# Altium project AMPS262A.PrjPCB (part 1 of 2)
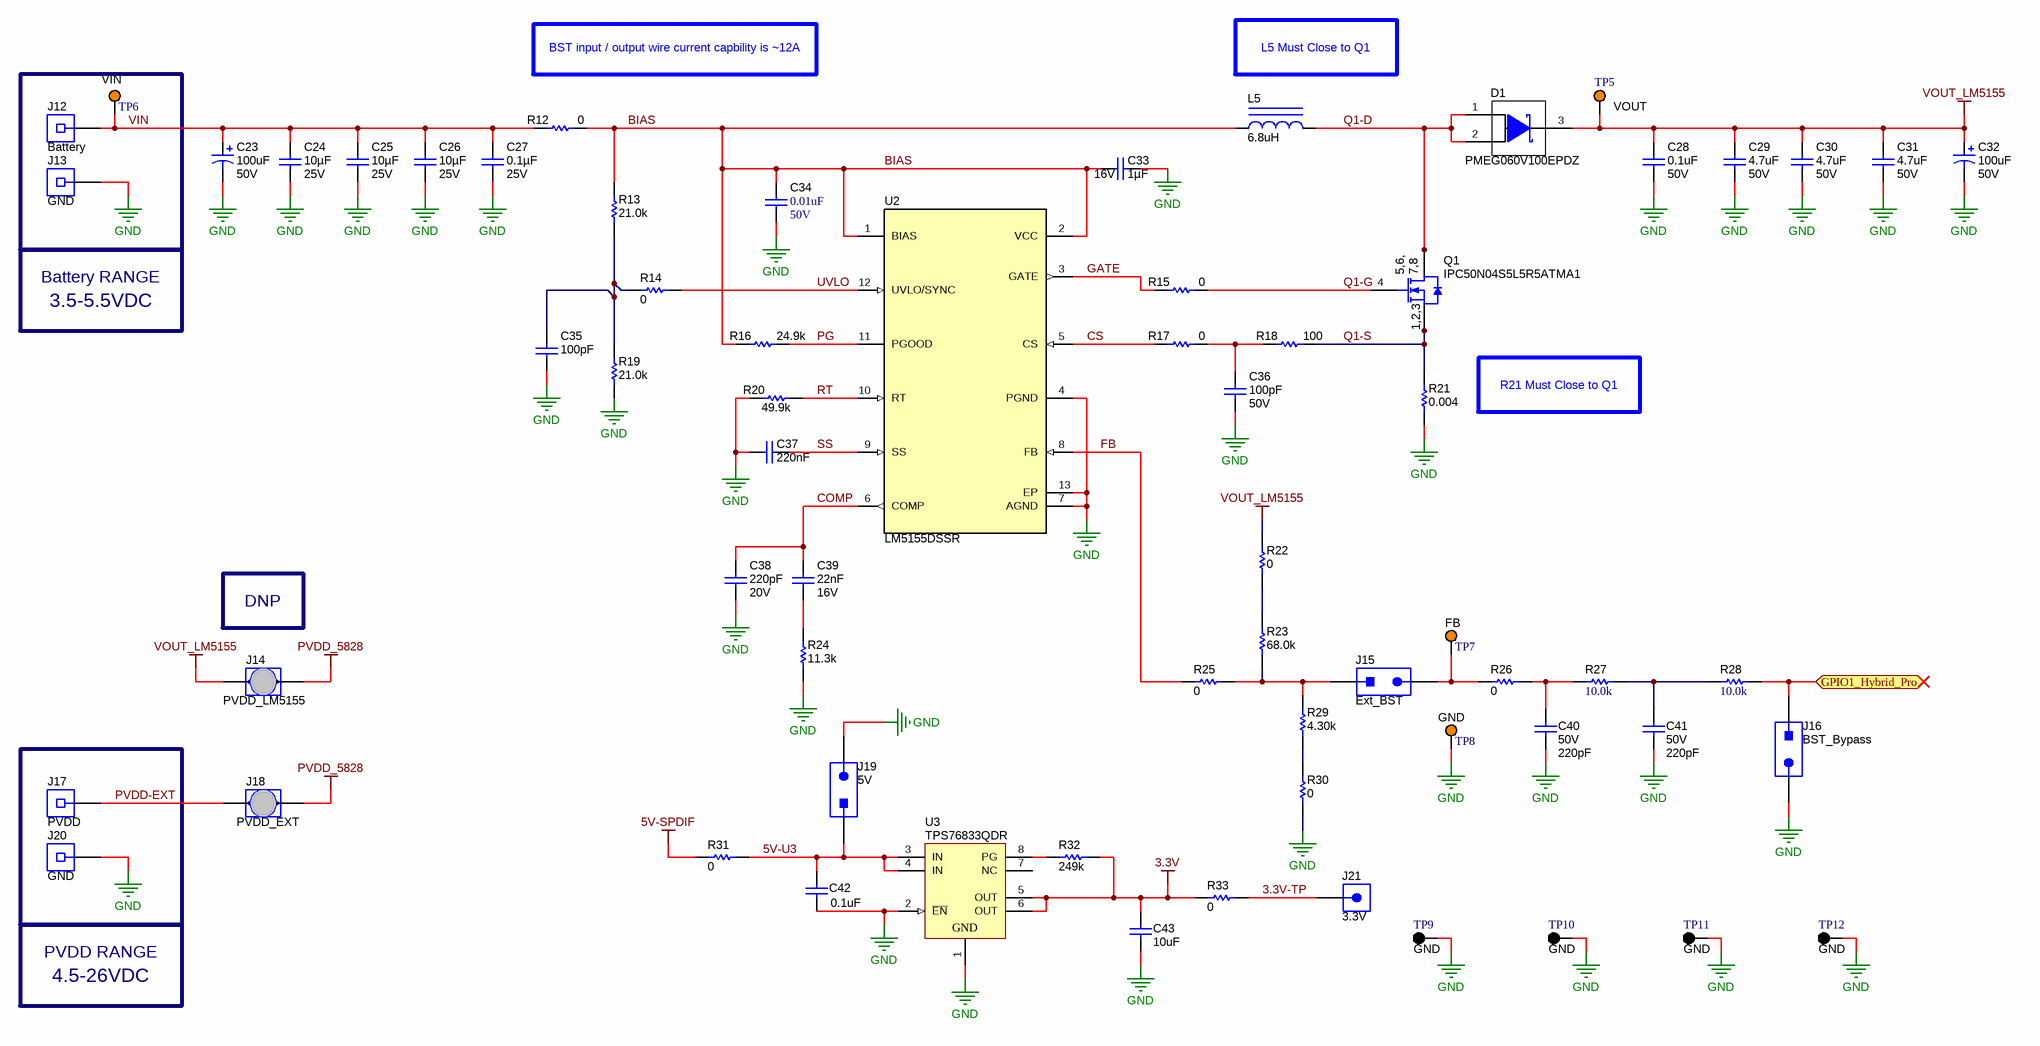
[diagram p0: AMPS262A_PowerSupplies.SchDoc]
CopyrightYear: 2021; PCB_Layout: Krypton Solutions; PCB_Rev: A; PRJ_Customer: Public Release; PRJ_Engineer: Ramsey Foote; PRJ_Number: AMPS262; PRJ_Title: TAS5830 Evaluation Module; SCH_Rev: A; TechSupport: http://www.ti.com/support; TID: N/A
5 sheets, 325 parts. Net scope: flat (ports and power ports of the same name join across sheets).
Board file: AMPS262A.PcbDoc
Sheets:
  AMPS262A_PowerSupplies.SchDoc
  AMPS262A_Hardware.SchDoc
  AMPS262A_USB.SchDoc
  AMPS262A_SPDIF_I2S_PSIA.SchDoc
  AMPS262A_TAS5830_IO.SchDoc

## Sheet AMPS262A_PowerSupplies.SchDoc
size A2; Date: Not shown in title block; ApprovedBy: Not shown in title block; CheckedBy: Not shown in title block; Author: Not shown in title block; CompanyName: Not shown in title block; Engineer: Not shown in title block; Organization: Not shown in title block; Address1: Not shown in title block; Address2: Not shown in title block; Address3: Not shown in title block; Address4: Not shown in title block; DocumentNumber: 2; Revision: Use project parameter SCH_Rev; SheetNumber: 1; SheetTotal: 5; PageSetup: Record=PageOptions¦CenterHorizontal=True¦CenterVertical=True¦PrintScale=1.00¦XCorrection=1.00¦YCorrection=1.00¦PrintKind=0¦BorderSize=5000000¦LeftOffset=0¦BottomOffset=0¦Orientation=2¦PaperLength=1000¦PaperWidth=1000¦Scale=100¦PaperSource=15¦PrintQuality=600¦MediaType=1¦DitherType=10¦PaperKind=Letter¦PrintScaleMode=1

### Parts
C23  VDC_V: 50V  ValueDisplayed: 100uF  [SM_RADIAL_10BMM]  (hidden comment: +)
C24  VDC_V: 25V  ValueDisplayed: 10µF  [0603L]  (hidden comment: GRM188R61E106KA73D)
C25  VDC_V: 25V  ValueDisplayed: 10µF  [0603L]  (hidden comment: GRM188R61E106KA73D)
C26  VDC_V: 25V  ValueDisplayed: 10µF  [0603L]  (hidden comment: GRM188R61E106KA73D)
C27  VDC_V: 25V  ValueDisplayed: 0.1µF  [0402L]  (hidden comment: CGA2B3X7R1E104K050BB)
C28  Cap_F: 0.1uF  VDC_V: 50V  [0603L]  (hidden comment: CGA3E2X7R1H104K080AA)
C29  VDC_V: 50V  ValueDisplayed: 4.7uF  [1210_280]  (hidden comment: CGA6P3X7R1H475K250AB)
C30  VDC_V: 50V  ValueDisplayed: 4.7uF  [1210_280]  (hidden comment: CGA6P3X7R1H475K250AB)
C31  VDC_V: 50V  ValueDisplayed: 4.7uF  [1210_280]  (hidden comment: CGA6P3X7R1H475K250AB)
C32  VDC_V: 50V  ValueDisplayed: 100uF  [HXB_JA0]  (hidden comment: +)
C33  Cap_F: 1µF  VDC_V: 16V  [0603L]  (hidden comment: GCM188R71C105MA64D)
C34  VDC_V: 50V  ValueDisplayed: 0.01uF  [0603L]  (hidden comment: GCM188R71H103KA37D)
C35  ValueDisplayed: 100pF  [0603L]  (hidden comment: DNP)
C36  VDC_V: 50V  ValueDisplayed: 100pF  [0603L]  (hidden comment: C0603C101F5GACTU)
C37  Cap_F: 220nF  [0603L]  (hidden comment: CGA3E3X7R1H224K080AB)
C38  VDC_V: 20V  ValueDisplayed: 220pF  [0603L]  (hidden comment: CGA3E2C0G1H221J080AA)
C39  Cap_F: 22nF  VDC_V: 16V  [0603L]  (hidden comment: C0603C223K4RACTU)
C40  VDC_V: 50V  ValueDisplayed: 220pF  [0402]  (hidden comment: CGA2B2C0G1H221J050BA)
C41  VDC_V: 50V  ValueDisplayed: 220pF  [0402]  (hidden comment: CGA2B2C0G1H221J050BA)
C42  ValueDisplayed: 0.1uF  [0402L]  (hidden comment: 885012205037)
C43  ValueDisplayed: 10uF  [0603L]  (hidden comment: Capacitor)
D1  PMEG060V100EPDZ  [SOT1289]
J12  Battery  [Keystone_7006]
J13  GND  [Keystone_7007]
J14  Note: PVDD_LM5155  [HARWIN_S1911-46R]  (hidden comment: DNP)
J15  Ext_BST  [Sullins_PBC02SAAN]
J16  BST_Bypass  [Sullins_PBC02SAAN]
J17  PVDD  [Keystone_7006]
J18  PVDD_EXT  [HARWIN_S1911-46R]
J19  5V  [Sullins_PBC02SAAN]
J20  GND  [Keystone_7007]
J21  3.3V  [CONN_1040]
L5  ValueDisplayed: 6.8uH  [XAL1010]  (hidden comment: XAL1010-682MEB)
Q1  IPC50N04S5L5R5ATMA1  [PG-TDSON-8-33]
R12  ValueDisplayed: 0  [2512_WIDE_VISHAY]  (hidden comment: RCL12250000Z0EG)
R13  ValueDisplayed: 21.0k  [0603]  (hidden comment: RC0603FR-0721KL)
R14  ValueDisplayed: 0  [0603L]  (hidden comment: RMCF0603ZT0R00)
R15  ValueDisplayed: 0  [0603L]  (hidden comment: RC0603JR-070RL)
R16  ValueDisplayed: 24.9k  [0603L]  (hidden comment: RC0603FR-0724K9L)
R17  ValueDisplayed: 0  [0603L]  (hidden comment: RC0603JR-070RL)
R18  ValueDisplayed: 100  [0603L]  (hidden comment: RC0603FR-07100RL)
R19  ValueDisplayed: 21.0k  [0603]  (hidden comment: RC0603FR-0721KL)
R20  ValueDisplayed: 49.9k  [0603L]  (hidden comment: CRCW060349K9FKEA)
R21  ValueDisplayed: 0.004  [ERJMS4S]  (hidden comment: ERJ-MS4SF4M0U)
R22  ValueDisplayed: 0  [0603L]  (hidden comment: RC0603JR-070RL)
R23  ValueDisplayed: 68.0k  [0603]  (hidden comment: RC0603FR-0768KL)
R24  ValueDisplayed: 11.3k  [0603L]  (hidden comment: CRCW060311K3FKEA)
R25  ValueDisplayed: 0  [0603L]  (hidden comment: RC0603JR-070RL)
R26  ValueDisplayed: 0  [0603L]  (hidden comment: RC0603JR-070RL)
R27  ValueDisplayed: 10.0k  [0603]  (hidden comment: ERJ-3EKF1002V)
R28  ValueDisplayed: 10.0k  [0603]  (hidden comment: ERJ-3EKF1002V)
R29  ValueDisplayed: 4.30k  [0603]  (hidden comment: RC0603FR-074K3L)
R30  ValueDisplayed: 0  [0603L]  (hidden comment: RC0603JR-070RL)
R31  ValueDisplayed: 0  [0805L]  (hidden comment: RC0805JR-070RL)
R32  ValueDisplayed: 249k  [0603L]  (hidden comment: RC0603FR-07249KL)
R33  ValueDisplayed: 0  [0805L]  (hidden comment: RC0805JR-070RL)
TP5  VOUT  [Keystone5003]
TP6  VIN  [Keystone5003]
TP7  FB  [Keystone5003]
TP8  GND  [Keystone5003]
TP9  GND  [Keystone5006]
TP10  GND  [Keystone5006]
TP11  GND  [Keystone5006]
TP12  GND  [Keystone5006]
U2  LM5155DSSR  [DSS0012B]
U3  PartNumber: TPS76833QDR  [D0008A_M]  (hidden comment: TI-TPS7XXXXD8_A)

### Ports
GPIO1_Hybrid_Pro (bidir)

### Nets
3.3V: C43.1 R32.2 R33.1 U3.5(OUT) U3.6(OUT)
5V-SPDIF: R31.1
GND: C23.2(-) C24.2 C25.2 C26.2 C27.2 C28.2 C29.2 C30.2 C31.2 C32.2(-) C33.1 C34.2 C35.2 C36.2 C37.1 C38.2 C40.2 C41.2 C42.1 C43.2 J13.1 J16.2 J19.2 J20.1 R19.1 R20.2 R21.1 R24.1 R30.1 TP8.1 TP9.1 TP10.1 TP11.1 TP12.1 U2.4(PGND) U2.7(AGND) U2.13(EP) U3.1(GND) U3.2(~{EN})
PVDD_5828: J14.2 J18.2
VOUT_LM5155: C28.1 C29.1 C30.1 C31.1 C32.1(+) D1.3(K) J14.1 R22.2 TP5.1
3.3V-TP: J21.1 R33.2
5V-U3: C42.2 J19.1 R31.2 U3.3(IN) U3.4(IN)
BIAS: C33.2 C34.1 L5.1 R12.2 R13.2 R16.1 U2.1(BIAS) U2.2(VCC)
COMP: C38.1 C39.1 U2.6(COMP)
CS: R17.1 U2.5(CS)
FB: R25.1 U2.8(FB)
GATE: R15.1 U2.3(GATE)
GPIO1_Hybrid_Pro: J16.1 R28.2 ; port GPIO1_Hybrid_Pro
PG: R16.2 U2.11(PGOOD)
PVDD-EXT: J17.1 J18.1
Q1-D: D1.1(A) D1.2(A) L5.2 Q1.5(D) Q1.6(D) Q1.7(D) Q1.8(D)
Q1-G: Q1.4(G) R15.2
Q1-S: Q1.1(S) Q1.2(S) Q1.3(S) R18.2 R21.2
RT: R20.1 U2.10(RT)
SS: C37.2 U2.9(SS)
UVLO: R14.2 U2.12(UVLO/SYNC)
VIN: C23.1(+) C24.1 C25.1 C26.1 C27.1 J12.1 R12.1 TP6.1
NetC35_1: C35.1 R13.1 R14.1 R19.2
NetC36_1: C36.1 R17.2 R18.1
NetC39_2: C39.2 R24.2
NetC40_1: C40.1 R26.2 R27.1
NetC41_1: C41.1 R27.2 R28.1
NetJ15_1: J15.1 R23.1 R25.2 R29.2
NetJ15_2: J15.2 R26.1 TP7.1
NetR22_1: R22.1 R23.2
NetR29_1: R29.1 R30.2
NetR32_1: R32.1 U3.8(PG)

Not connected (* = marked no-connect by the designer): U3 7(NC)

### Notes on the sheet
- BST input / output wire current capbility is
  2A
- L5 Must Close to Q1
- Battery RANGE
- 3.5-5.5VDC
- R21 Must Close to Q1
- DNP
- PVDD RANGE
- 4.5-26VDC

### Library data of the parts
C23 = CMP-0012596-3: CAP, Polymer Hybrid, 100 uF, 50 V, +/- 20%, 28 ohm, 10x10 SMD; Manufacturer: Panasonic; PartNumber: EEHZC1H101P; Alternate Manufacturer: Cornell Dubilier Electronics (CDE); Alternate PartNumber: HZA107M050G24VT-F; TaMin_C: -55°C; ESR_ohm: 28; Polarized: Y; SizeAreaWB_mm2: 159.9; Value1: 28 ohm; Value: 100uF; TaMax_C: 125°C; SizeZ_mm: 10.2; SizeX_mm: 11; SizeY_mm: 10.3; SizeArea_mm2: 113.3; CompType: Capacitor; Cap_F: 100µF; IRMS_A: 1.6A; AEC Category: Q200
C24-C26 = CMP-0860569-1: CAP, CERM, 10 µF, 25 V,+/- 10%, X5R, 0603; Alternate Manufacturer: CAL-CHIP ELECTRONICS, INC.; Manufacturer: MuRata; Alternate PartNumber: GMC10X5R106K25NT; SizeZ_mm: 1; AEC Category: Q200; AEC Qualified: N; TaMin_C: -55°C; Cap_Case: 0603; SizeY_mm: 0.8; SizeAreaWB_mm2: 4.68; SizeArea_mm2: 1.28; TaMax_C: 85°C; SizeX_mm: 1.6; Value: 10uF; U/M: EA
C27 = CMP-0080610-1: CAP, CERM, 0.1 µF, 25 V,+/- 10%, X7R, AEC-Q200 Grade 1, 0402; Manufacturer: TDK; TaMin_C: -55°C; Polarized: N; SizeAreaWB_mm2: 3; U/M: EA; Value: 0.1uF; TaMax_C: 125°C; SizeZ_mm: 0.6; SizeX_mm: 1; SizeY_mm: 0.5; Cap_Case: 0402; AEC Qualified: Y; Cap_F: 100nF; AEC Category: Q200
C28 = CMP-0007078-4: CAP, CERM, 0.1 uF, 50 V, +/- 10%, X7R, AEC-Q200 Grade 1, 0603; Manufacturer: TDK; TaMin_C: -55°C; ESR_ohm: 0.0296; Polarized: N; SizeAreaWB_mm2: 4.68; Value1: 0.0296 ohm; U/M: EA; Value: 0.1uF; TaMax_C: 125°C; SizeZ_mm: 1; SizeX_mm: 1.6; SizeY_mm: 0.8; Cap_Case: 0603; SizeArea_mm2: 1.28; AEC Qualified: Y; IRMS_A: 971.99mA; AEC Category: Q200
C29-C31 = CMP-0009162-2: CAP, CERM, 4.7 uF, 50 V, +/- 10%, X7R, AEC-Q200 Grade 1, 1210; Manufacturer: TDK; TaMin_C: -55°C; ESR_ohm: 3.166m; Polarized: N; SizeAreaWB_mm2: 14.7; Value1: 0.003166 ohm; U/M: EA; Value: 4.7uF; TaMax_C: 125°C; SizeZ_mm: 2.8; SizeX_mm: 3.2; SizeY_mm: 2.5; SizeArea_mm2: 8; AEC Qualified: Y; Cap_F: 4.7µF; IRMS_A: 4.13311A; AEC Grade: 1; AEC Category: Q200
C32 = CMP-0012269-3: CAP, Aluminum Polymer, 100 uF, 50 V, +/- 20%, 0.025 ohm, AEC-Q200 Grade 2, D10xL10mm SMD; Manufacturer: Chemi-Con; PartNumber: HHXB500ARA101MJA0G; Alternate Manufacturer: Cornell Dubilier Electronics (CDE); Alternate PartNumber: HZA107M050G24VT-F; TaMin_C: -55°C; ESR_ohm: 0.025; Polarized: Y; Value: 100uF; TaMax_C: 105°C; Cap_Case: 10x10mm; CompType: Capacitor; Cap_F: 100µF; IRMS_A: 2A; AEC Grade: 2; AEC Category: Q200
C33 = CMP-0007137-5: CAP, CERM, 1 uF, 16 V, +/- 20%, X7R, AEC-Q200 Grade 1, 0603; Manufacturer: MuRata; TaMin_C: -55°C; Polarized: N; SizeAreaWB_mm2: 4.68; Value1: Unknown; U/M: EA; Value: 1uF; TaMax_C: 125°C; SizeZ_mm: 1; SizeX_mm: 1.6; SizeY_mm: 0.8; Cap_Case: 0603; SizeArea_mm2: 1.28; AEC Qualified: Y; AEC Category: Q200
C34 = CMP-0007143-4: CAP, CERM, 0.01 uF, 50 V, +/- 10%, X7R, AEC-Q200 Grade 1, 0603; Manufacturer: MuRata; TaMin_C: -55°C; Polarized: N; SizeAreaWB_mm2: 4.68; Value1: Unknown; U/M: EA; Value: 0.01uF; TaMax_C: 125°C; SizeZ_mm: 1; SizeX_mm: 1.6; SizeY_mm: 0.8; Cap_Case: 0603; SizeArea_mm2: 1.28; AEC Qualified: Y; Cap_F: 10nF; AEC Category: Q200
C35 = CMP-0080091-1: CAP, CERM, 100 pF, 50 V,+/- 1%, C0G/NP0, 0603; PartNumber: C0603C101F5GACTU; Manufacturer: Kemet; SizeAreaWB_mm2: 4.68; SizeArea_mm2: 1.28; AEC Qualified: N; AEC Category: Q200; Value: 100pF; TaMax_C: 125°C; SizeZ_mm: 1; Green_REACh: Passed; TaMin_C: -55°C; VDC_V: 50V; SizeY_mm: 0.8; Green_Lifecycle: Active; U/M: EA; SizeX_mm: 1.6; Cap_Case: 0603
C36 = CMP-0080091-1: CAP, CERM, 100 pF, 50 V,+/- 1%, C0G/NP0, 0603; Manufacturer: Kemet; SizeAreaWB_mm2: 4.68; SizeArea_mm2: 1.28; AEC Qualified: N; AEC Category: Q200; Value: 100pF; TaMax_C: 125°C; SizeZ_mm: 1; Green_REACh: Passed; TaMin_C: -55°C; SizeY_mm: 0.8; Green_Lifecycle: Active; U/M: EA; SizeX_mm: 1.6; Cap_Case: 0603
C37 = CMP-0007094-5: CAP, CERM, 0.22 uF, 50 V, +/- 10%, X7R, AEC-Q200 Grade 1, 0603; Manufacturer: TDK; TaMin_C: -55°C; ESR_ohm: 0.021699; Polarized: N; SizeAreaWB_mm2: 4.68; Value1: 0.021699 ohm; U/M: EA; Value: 0.22uF; TaMax_C: 125°C; SizeZ_mm: 1; SizeX_mm: 1.6; SizeY_mm: 0.8; Cap_Case: 0603; Value2: 50V; SizeArea_mm2: 1.28; AEC Qualified: Y; IRMS_A: 1.12496A; AEC Category: Q200
C38 = CMP-0007072-4: CAP, CERM, 220 pF, 20 V, +/- 5%, C0G/NP0, AEC-Q200 Grade 1, 0603; Manufacturer: TDK; TaMin_C: -55°C; Polarized: N; SizeAreaWB_mm2: 4.68; Value1: Unknown; U/M: EA; Value: 220pF; TaMax_C: 125°C; SizeZ_mm: 1; SizeX_mm: 1.6; SizeY_mm: 0.8; Cap_Case: 0603; SizeArea_mm2: 1.28; AEC Qualified: Y; AEC Category: Q200
C39 = CMP-0006900-4: CAP, CERM, 0.022 uF, 16 V, +/- 10%, X7R, 0603; Manufacturer: Kemet; TaMin_C: -55°C; Polarized: N; SizeAreaWB_mm2: 4.68; Value1: Unknown; U/M: EA; TaMax_C: 125°C; SizeZ_mm: 1; SizeX_mm: 1.6; SizeY_mm: 0.8; Cap_Case: 0603; SizeArea_mm2: 1.28; AEC Category: Q200
C40 C41 = CMP-0079606-1: CAP, CERM, 220 pF, 50 V,+/- 5%, C0G/NP0, AEC-Q200 Grade 1, 0402; Manufacturer: TDK; TaMin_C: -55°C; Polarized: N; SizeAreaWB_mm2: 3; U/M: EA; Value: 220pF; TaMax_C: 125°C; SizeZ_mm: 0.6; SizeX_mm: 1; SizeY_mm: 0.5; AEC Qualified: Y; AEC Category: Q200
C42 = CMP-0006228-2: CAP, CERM, 0.1 uF, 16 V, +/- 10%, X7R, 0402; Manufacturer: Wurth Elektronik; TaMin_C: -55°C; Polarized: N; SizeAreaWB_mm2: 3; Value1: Unknown; U/M: EA; Value: 0.1uF; TaMax_C: 125°C; SizeZ_mm: 0.6; SizeX_mm: 1; SizeY_mm: 0.5; Cap_Case: 0402; Value2: 16V; Cap_F: 100nF; AEC Category: Q200
C43 = CMP-0007003-5: CAP, CERM, 10 uF, 10 V, +/- 20%, X5R, 0603; PartNumber: C1608X5R1A106M080AC; Manufacturer: TDK; Polarized: N; Value: 10uF; U/M: EA; Cap_F: 10µF; ESR_ohm: 7.8m; Value1: 0.0078 ohm; VDC_V: 10V; IRMS_A: 1.85A; TaMin_C: -55°C; TaMax_C: 85°C; Cap_Case: 0603; SizeArea_mm2: 1.28; SizeAreaWB_mm2: 4.68; SizeX_mm: 1.6; SizeY_mm: 0.8; SizeZ_mm: 1; AEC Category: Q200
D1 = CMP-0028984-3: Diode, Schottky, 60 V, 10 A, AEC-Q101, CFP15; Manufacturer: Nexperia; Alternate Manufacturer: Vishay General Semiconductor - Diodes Division; Alternate PartNumber: V10PM6-M3/H; SizeArea_mm2: 27.95; SizeY_mm: 4.3; Vr_V: 60V; Value2: 0.56V; SizeX_mm: 6.5; SizeZ_mm: 0.82; AEC Category: Q101; Value1: 10A; Vf_V: 560mV; AEC Qualified: Y; SizeAreaWB_mm2: 53.55; TJmax_C: 175°C; Value: 60V
J12 J17 = CMP-0055127-1: Binding Post, RED, TH; PartNumber: 7006; Manufacturer: Keystone; CompType: Connector; Green_Lifecycle: Active; Green_REACh: Passed; CNHeader: FALSE
J13 J20 = CMP-0055128-1: Binding Post, BLACK, TH; PartNumber: 7007; Manufacturer: Keystone; CompType: Connector; Green_Lifecycle: Active; Green_REACh: Passed; CNHeader: FALSE
J14 J18 = CMP-0075020-1: JUMPER TIN SMD; Manufacturer: Harwin; PartNumber: S1911-46R; CNHeader: False; Green_Lifecycle: Active; Green_REACh: Passed; CompType: Jumper SMT
J15 J16 J19 = CMP-0054566-1: Header, 100mil, 2x1, Gold, TH; PartNumber: PBC02SAAN; Manufacturer: Sullins Connector Solutions; Pitch_mm: 2.54; Gender: Male; Shrouded: N; Row_Count: 1; Current_A: 3A; Voltage_V: 1.8kV; Cert_UL: Y; CNHeader: TRUE; CT: FALSE; Green_Lifecycle: Active; Green_REACh: Passed
J21 = CMP-0055161-1: Manufacturer: Keystone; PartNumber: 1040; CNHeader: FALSE; Green_Lifecycle: Active; Green_REACh: Passed; CompType: Test Point; CT: TRUE
L5 = CMP-0060953-1: Inductor, Shielded, Composite, 6.8 uH, 18.5 A, 0.01 ohm, SMD; Manufacturer: Coilcraft; Isat: 21.8A @ 30% inductance drop; Irms: 18.5A @ 40C rise; Green_Lifecycle: Not Set; SizeAreaWB_mm2: 159.6; DCR_ohm: 0.01; Green_REACh: Incomplete; Value: 6.8uH; Imax_A: 18.5A; SizeZ_mm: 10; SizeX_mm: 11.3; SizeArea_mm2: 113; Ind_H: 6.8µH; AEC Category: Q200
Q1 = CMP-0080659-3: MOSFET, N-CH, 40 V, 50 A, AEC-Q101, SON-8; Alternate PartNumber: CSD18510Q5B; Manufacturer: Infineon Technologies; Alternate Manufacturer: Texas Instruments; Value1: 0.0079 ohm; IdsMax_A: 50A; SizeZ_mm: 1.1; QgTyp_nC: 17; SizeX_mm: 6.44; AEC Category: Q101; Rdson45_ohm: 7.9m; VdsMax_V: 40V; Value: 40V; Value2: 17 nC; SizeAreaWB_mm2: 60.35; ChMode: Enhancement; SizeArea_mm2: 33.17; SizeY_mm: 5.15; Vgs_V: 16V; ChType: N; AEC Qualified: Y
R12 = CMP-0015368-2: RES, 0, 5%, 2 W, 2512 WIDE; Manufacturer: Vishay Draloric; Power_W: 2W; TempCo: ppm/C; Value_Code: 0000; U/M: EA; Value: 0; EIA_Code: E24; AEC Category: Q200
R13 R19 = CMP-0022914-5: RES, 21.0 k, 1%, 0.1 W, 0603; Manufacturer: Yageo; Power_W: 100mW; TempCo: 100 ppm/C; Value_Code: 21k0; Value: 21.0k; EIA_Code: E96; Res_ohm: 21k; SizeX_mm: 1.6; SizeY_mm: 0.8; SizeZ_mm: 1; Value2: 0.1W; SizeArea_mm2: 1.28; AEC Qualified: N; VDC_V: 75V; AEC Category: Q200; SizeAreaWB_mm2: 4.68
R14 = CMP-0023343-3: RES, 0, 1%, 0.1 W, AEC-Q200 Grade 0, 0603; Manufacturer: Stackpole Electronics Inc; Power_W: 100mW; TempCo: ppm/C; U/M: EA; Value: 0; SizeX_mm: 1.6; SizeY_mm: 0.8; SizeZ_mm: 1; Value2: 0.1W; SizeArea_mm2: 1.28; AEC Qualified: Y; AEC Category: Q200
R15 R17 R22 R25 R26 R30 = CMP-0025885-5: RES, 0, 5%, 0.1 W, 0603; Manufacturer: Yageo; Power_W: 100mW; TempCo: 200 ppm/C; Value_Code: 0000; Value: 0; EIA_Code: E24; SizeX_mm: 1.6; SizeZ_mm: 1; Value2: 0.1W; SizeArea_mm2: 1.28; AEC Qualified: N; VDC_V: 75V; AEC Category: Q200; SizeY_mm: 0.8; SizeAreaWB_mm2: 4.68
R16 = CMP-0022944-5: RES, 24.9 k, 1%, 0.1 W, 0603; Manufacturer: Yageo; Power_W: 100mW; TempCo: 100 ppm/C; Value_Code: 24k9; Value: 24.9k; EIA_Code: E96; SizeX_mm: 1.6; SizeY_mm: 0.8; SizeZ_mm: 1; Value2: 0.1W; SizeArea_mm2: 1.28; AEC Qualified: N; VDC_V: 75V; AEC Category: Q200; SizeAreaWB_mm2: 4.68
R18 = CMP-0022736-4: RES, 100, 1%, 0.1 W, 0603; Manufacturer: Yageo; Power_W: 100mW; TempCo: 100 ppm/C; Value_Code: 100R; Value: 100; EIA_Code: E96; SizeX_mm: 1.6; SizeY_mm: 0.8; SizeZ_mm: 1; Value2: 0.1W; SizeArea_mm2: 1.28; AEC Qualified: N; VDC_V: 75V; AEC Category: Q200; SizeAreaWB_mm2: 4.68
R20 = CMP-0022447-4: RES, 49.9 k, 1%, 0.1 W, AEC-Q200 Grade 0, 0603; Manufacturer: Vishay-Dale; Power_W: 100mW; TempCo: 100 ppm/C; Value_Code: 49k9; Value: 49.9k; EIA_Code: E96; SizeX_mm: 1.6; SizeY_mm: 0.8; SizeZ_mm: 1; Value2: 0.1W; SizeArea_mm2: 1.28; AEC Qualified: Y; VDC_V: 75V; AEC Category: Q200; AEC Grade: 0
R21 = CMP-0015077-2: RES, 0.004, 1%, 3 W, AEC-Q200 Grade 0, 6.4x3.2mm; Manufacturer: Panasonic; Alternate Manufacturer: TE Connectivity Passive Product; Alternate PartNumber: TLRP3A30WR004FTE; Power_W: 3W; TempCo: 75 ppm/C; SizeAreaWB_mm2: 43.68; Value_Code: 4L000; U/M: EA; Value: 0.004; Res_ohm: 4m; SizeX_mm: 6.4; SizeY_mm: 3.2; SizeZ_mm: 1.35; SizeArea_mm2: 20.48; AEC Qualified: Y; AEC Grade: 0; AEC Category: Q200
R23 = CMP-0023239-5: RES, 68.0 k, 1%, 0.1 W, 0603; Manufacturer: Yageo; Power_W: 100mW; TempCo: 100 ppm/C; Value_Code: 68k0; Value: 68.0k; Res_ohm: 68k; SizeX_mm: 1.6; SizeY_mm: 0.8; SizeZ_mm: 1; Value2: 0.1W; SizeArea_mm2: 1.28; AEC Qualified: N; VDC_V: 75V; AEC Category: Q200; SizeAreaWB_mm2: 4.68
R24 = CMP-0022017-4: RES, 11.3 k, 1%, 0.1 W, AEC-Q200 Grade 0, 0603; Manufacturer: Vishay-Dale; Power_W: 100mW; TempCo: 100 ppm/C; Value_Code: 11k3; Value: 11.3k; EIA_Code: E96; SizeX_mm: 1.6; SizeY_mm: 0.8; SizeZ_mm: 1; Value2: 0.1W; SizeArea_mm2: 1.28; AEC Qualified: Y; VDC_V: 75V; AEC Category: Q200; AEC Grade: 0
R27 R28 = CMP-0022684-3: RES, 10.0 k, 1%, 0.1 W, 0603; Manufacturer: Panasonic; Power_W: 100mW; TempCo: 100 ppm/C; Value_Code: 10k0; Value: 10.0k; EIA_Code: E96; Res_ohm: 10k; SizeX_mm: 1.6; SizeY_mm: 0.8; SizeZ_mm: 1; Value2: 0.1W; SizeArea_mm2: 1.28; AEC Category: Q200; VDC_V: 75V; U/M: EA
R29 = CMP-0023148-5: RES, 4.30 k, 1%, 0.1 W, 0603; Manufacturer: Yageo; Power_W: 100mW; TempCo: 100 ppm/C; Value_Code: 4k30; Value: 4.30k; Res_ohm: 4.3k; SizeX_mm: 1.6; SizeY_mm: 0.8; SizeZ_mm: 1; Value2: 0.1W; SizeArea_mm2: 1.28; AEC Qualified: N; VDC_V: 75V; AEC Category: Q200; SizeAreaWB_mm2: 4.68
R31 R33 = CMP-0020803-2: RES, 0, 5%, 0.125 W, 0805; Manufacturer: Yageo America; Power_W: 125mW; TempCo: 200 ppm/C; Value_Code: 0000; U/M: EA; Value: 0; EIA_Code: E24; SizeX_mm: 2; SizeY_mm: 1.25; SizeZ_mm: 1.45; Value2: 0.125W; SizeArea_mm2: 2.5; VDC_V: 150V; AEC Category: Q200
R32 = CMP-0022941-4: RES, 249 k, 1%, 0.1 W, 0603; Manufacturer: Yageo; Power_W: 100mW; TempCo: 100 ppm/C; Value: 249k; EIA_Code: E96; SizeX_mm: 1.6; SizeY_mm: 0.8; SizeZ_mm: 1; Value2: 0.1W; SizeArea_mm2: 1.28; AEC Qualified: N; VDC_V: 75V; AEC Category: Q200; SizeAreaWB_mm2: 4.68
TP5-TP8 = CMP-0055140-2: Test Point, Miniature, Orange, TH; Manufacturer: Keystone Electronics; ContactFinish: Silver; CNHeader: FALSE; CT: TRUE; Green_Lifecycle: Active; Green_REACh: Passed
TP9-TP12 = CMP-0055143-2: Test Point, Compact, Black, TH; Manufacturer: Keystone Electronics; CNHeader: FALSE; ContactFinish: Silver; CT: TRUE; Green_Lifecycle: Active; Green_REACh: Passed
U2 = CMP-0085413-1: 2.2-MHz Wide Input Nonsynchronous Boost, Sepic, Flyback Controller, DSS0012B (WSON-12); Alternate Manufacturer: Texas Instruments; Alternate PartNumber: LM5155DSST; SizeAreaWB_mm2: 12; SizeX_mm: 2; SizeZ_mm: 0.8; CompType: IC; SizeArea_mm2: 6; AEC Category: Q200; AEC Qualified: N; SizeY_mm: 3
U3 = CMP-0036485-1: Single Output Fast Transient Response LDO, 1 A, Fixed 3.3 V Output, 2.7 to 10 V Input, with Low IQ, 8-pin SOIC (D), -40 to 125 degC, Green (RoHS & no Sb/Br); Manufacturer: Texas Instruments; Accuracy(%): 2; Fixed Output Options(V): 3.3; Iout(Max)(A): 1; Iq(Typ)(mA): 0.08; Power Good: TRUE; SubFamily: Single Channel LDO; Vdo(Typ)(mV): 350; Vin(Max)(V): 10; Vin(Min)(V): 2.7

## Sheet AMPS262A_Hardware.SchDoc
size A4; Date: Not shown in title block; ApprovedBy: Not shown in title block; CheckedBy: Not shown in title block; Author: Not shown in title block; CompanyName: Not shown in title block; Engineer: Not shown in title block; Organization: Not shown in title block; Address1: Not shown in title block; Address2: Not shown in title block; Address3: Not shown in title block; Address4: Not shown in title block; DocumentNumber: 2; Revision: Use project parameter SCH_Rev; SheetNumber: 2; SheetTotal: 5; PageSetup: Record=PageOptions¦CenterHorizontal=True¦CenterVertical=True¦PrintScale=1.00¦XCorrection=1.00¦YCorrection=1.00¦PrintKind=0¦BorderSize=5000000¦LeftOffset=0¦BottomOffset=0¦Orientation=2¦PaperLength=1000¦PaperWidth=1000¦Scale=100¦PaperSource=15¦PrintQuality=600¦MediaType=1¦DitherType=10¦PaperKind=Letter¦PrintScaleMode=1
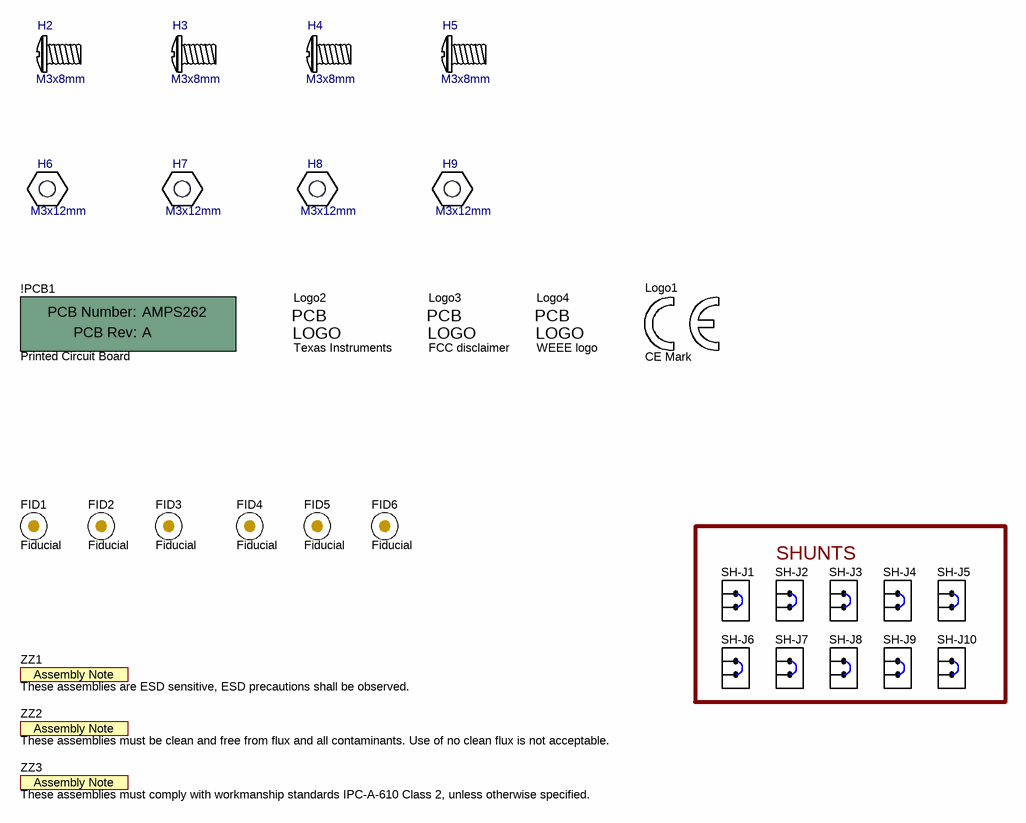
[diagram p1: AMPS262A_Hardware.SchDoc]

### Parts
!PCB1  Printed Circuit Board  (mechanical)
FID1  CompType: Fiducial  [Fiducial6.4-20]  (hidden comment: DNP)
FID2  CompType: Fiducial  [Fiducial6.4-20]  (hidden comment: DNP)
FID3  CompType: Fiducial  [Fiducial6.4-20]  (hidden comment: DNP)
FID4  CompType: Fiducial  [Fiducial6.4-20]  (hidden comment: DNP)
FID5  CompType: Fiducial  [Fiducial6.4-20]  (hidden comment: DNP)
FID6  CompType: Fiducial  [Fiducial6.4-20]  (hidden comment: DNP)
H2  M3x8mm  [APM_RM3X8MM 2701]
H3  M3x8mm  [APM_RM3X8MM 2701]
H4  M3x8mm  [APM_RM3X8MM 2701]
H5  M3x8mm  [APM_RM3X8MM 2701]
H6  M3x12mm  [Keystone_24434]
H7  M3x12mm  [Keystone_24434]
H8  M3x12mm  [Keystone_24434]
H9  M3x12mm  [Keystone_24434]
Logo1  CE Mark  [CE_Mark_5mm]  (no BOM)
Logo2  Texas Instruments  [TI_Stacked_Overlay_Small]  (no BOM)
Logo3  FCC disclaimer  [FCC_disclaimer_stacked]  (no BOM)
Logo4  WEEE logo  [WEEE_Minimum]  (no BOM)
SH-J1  SNT-100-BK-G  [SNT-100-BK-G]  (value not drawn)
SH-J2  SNT-100-BK-G  [SNT-100-BK-G]  (value not drawn)
SH-J3  SNT-100-BK-G  [SNT-100-BK-G]  (value not drawn)
SH-J4  SNT-100-BK-G  [SNT-100-BK-G]  (value not drawn)
SH-J5  SNT-100-BK-G  [SNT-100-BK-G]  (value not drawn)
SH-J6  SNT-100-BK-G  [SNT-100-BK-G]  (value not drawn)
SH-J7  SNT-100-BK-G  [SNT-100-BK-G]  (value not drawn)
SH-J8  SNT-100-BK-G  [SNT-100-BK-G]  (value not drawn)
SH-J9  SNT-100-BK-G  [SNT-100-BK-G]  (value not drawn)
SH-J10  SNT-100-BK-G  [SNT-100-BK-G]  (value not drawn)
ZZ1  These assemblies are ESD sensitive, ESD precautions shall be observed.  [AssemblyNote]  (no BOM)
ZZ2  These assemblies must be clean and free from flux and all contaminants. Use of no clean flux is not acceptable.  [AssemblyNote]  (no BOM)
ZZ3  These assemblies must comply with workmanship standards IPC-A-610 Class 2, unless otherwise specified.  [AssemblyNote]  (no BOM)

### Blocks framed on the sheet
SHUNTS: SH-J1-SH-J10

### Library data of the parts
!PCB1 = CMP-0003618-2: PartNumber: AMPS262; Manufacturer: Any
FID1-FID6 = CMP-0077181-1: Fiducial mark.  There is nothing to buy or mount.
H2-H5 = CMP-0003717-1: MACHINE SCREW PAN PHILLIPS M3; Manufacturer: APM HEXSEAL; Key: RM3X8MM 2701; CompType: Standoff
H6-H9 = CMP-0003665-1: Standoff, Hex, 12mm, M3, Aluminum; Manufacturer: Keystone; Key: 24434
Logo1 = CMP-0074844-2: Manufacturer: Texas Instruments; SymbolCreator: a0412235; AEC Category: Q200; CompType: IC
Logo2 = CMP-0074838-1: Texas Instrument Corporate Signature; Library Reference: Logo; SymbolCreator: a0412235; Lib Reference: TI_Logo
Logo3 = CMP-0074847-1: FCC_disclaimer; Library Reference: Logo
Logo4 = CMP-0074769-4: Manufacturer: Texas Instruments; CompType: IC; AEC Category: Q200
SH-J1-SH-J10 = CMP-0003623-3: Shunt, 100mil, Gold plated, Black; Alternate PartNumber: 969102-0000-DA; Manufacturer: Samtec; Alternate Manufacturer: 3M; Value: 1x2
ZZ1 = CMP-0077236-1
ZZ2 = CMP-0077237-1
ZZ3 = CMP-0077238-1

## Sheet AMPS262A_USB.SchDoc
size A2; Date: Not shown in title block; ApprovedBy: Not shown in title block; CheckedBy: Not shown in title block; Author: Not shown in title block; CompanyName: Not shown in title block; Engineer: Not shown in title block; Organization: Not shown in title block; Address1: Not shown in title block; Address2: Not shown in title block; Address3: Not shown in title block; Address4: Not shown in title block; DocumentNumber: 2; Revision: Use project parameter SCH_Rev; SheetNumber: 3; SheetTotal: 5; PageSetup: Record=PageOptions¦CenterHorizontal=True¦CenterVertical=True¦PrintScale=1.00¦XCorrection=1.00¦YCorrection=1.00¦PrintKind=0¦BorderSize=5000000¦LeftOffset=0¦BottomOffset=0¦Orientation=2¦PaperLength=1000¦PaperWidth=1000¦Scale=100¦PaperSource=15¦PrintQuality=600¦MediaType=1¦DitherType=10¦PaperKind=Letter¦PrintScaleMode=1
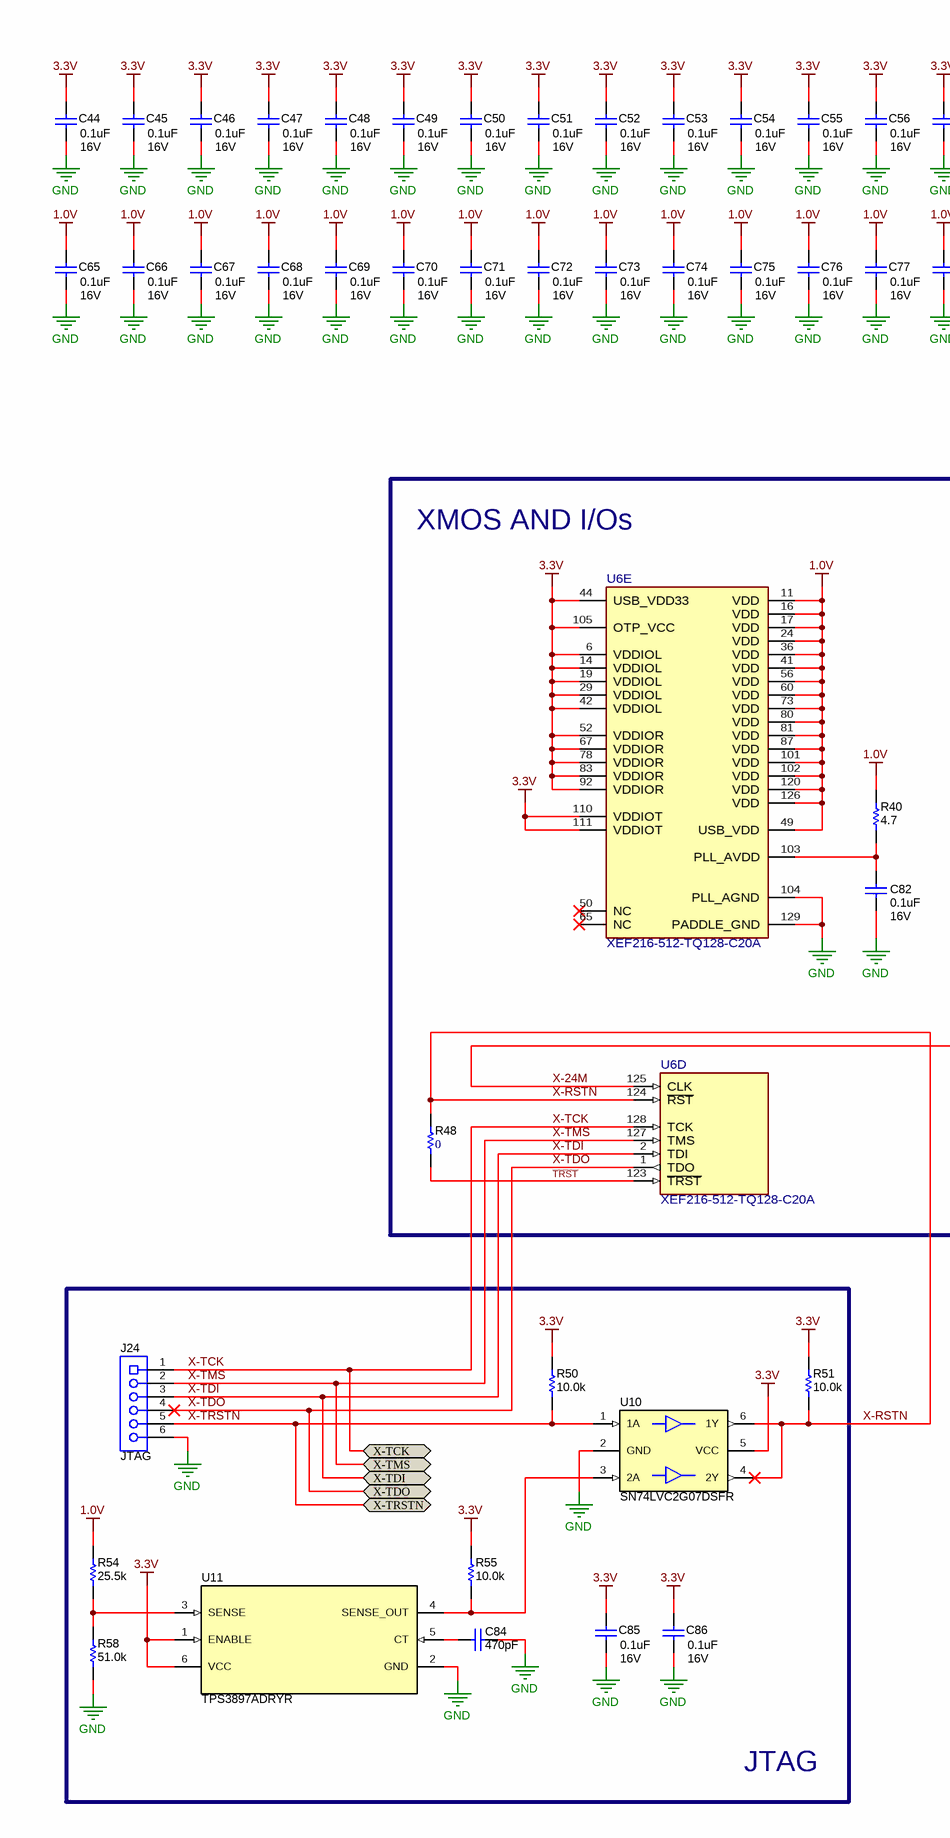
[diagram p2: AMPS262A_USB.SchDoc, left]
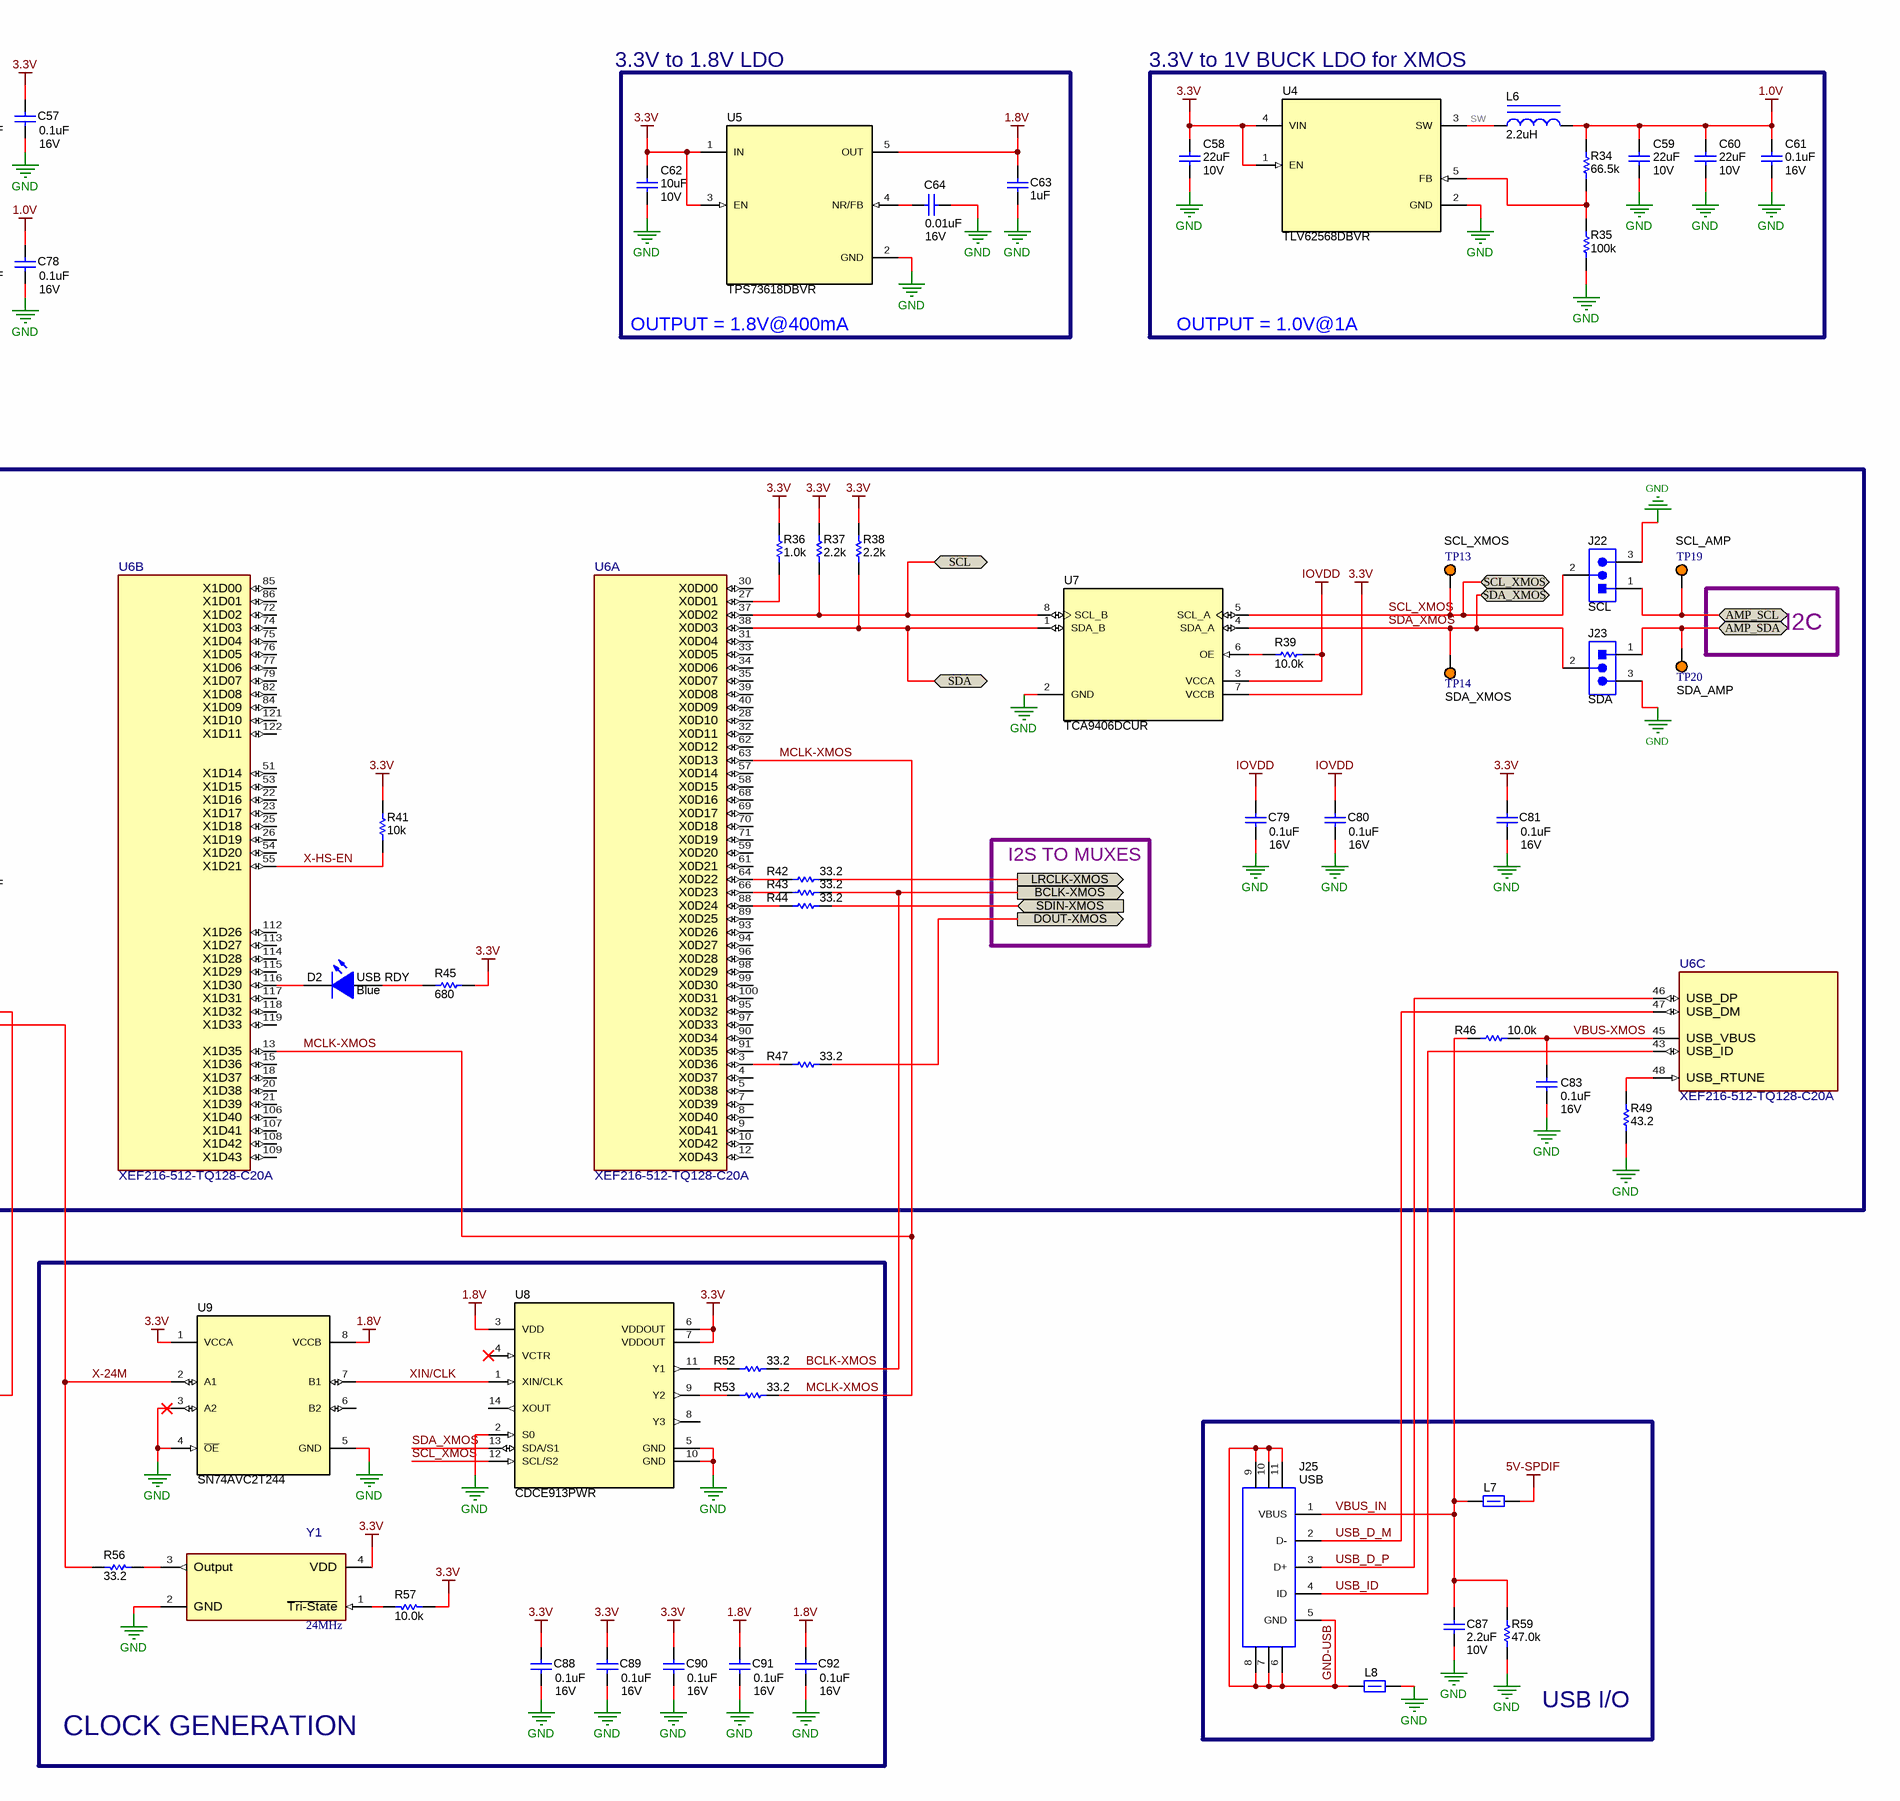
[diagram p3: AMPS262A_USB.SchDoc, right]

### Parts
C44  VDC_V: 16V  ValueDisplayed: 0.1uF  [0402L]  (hidden comment: 885012205037)
C45  VDC_V: 16V  ValueDisplayed: 0.1uF  [0402L]  (hidden comment: 885012205037)
C46  VDC_V: 16V  ValueDisplayed: 0.1uF  [0402L]  (hidden comment: 885012205037)
C47  VDC_V: 16V  ValueDisplayed: 0.1uF  [0402L]  (hidden comment: 885012205037)
C48  VDC_V: 16V  ValueDisplayed: 0.1uF  [0402L]  (hidden comment: 885012205037)
C49  VDC_V: 16V  ValueDisplayed: 0.1uF  [0402L]  (hidden comment: 885012205037)
C50  VDC_V: 16V  ValueDisplayed: 0.1uF  [0402L]  (hidden comment: 885012205037)
C51  VDC_V: 16V  ValueDisplayed: 0.1uF  [0402L]  (hidden comment: 885012205037)
C52  VDC_V: 16V  ValueDisplayed: 0.1uF  [0402L]  (hidden comment: 885012205037)
C53  VDC_V: 16V  ValueDisplayed: 0.1uF  [0402L]  (hidden comment: 885012205037)
C54  VDC_V: 16V  ValueDisplayed: 0.1uF  [0402L]  (hidden comment: 885012205037)
C55  VDC_V: 16V  ValueDisplayed: 0.1uF  [0402L]  (hidden comment: 885012205037)
C56  VDC_V: 16V  ValueDisplayed: 0.1uF  [0402L]  (hidden comment: 885012205037)
C57  VDC_V: 16V  ValueDisplayed: 0.1uF  [0402L]  (hidden comment: 885012205037)
C58  VDC_V: 10V  ValueDisplayed: 22uF  [0603L]  (hidden comment: C1608X5R1A226M080AC)
C59  VDC_V: 10V  ValueDisplayed: 22uF  [0603L]  (hidden comment: C1608X5R1A226M080AC)
C60  VDC_V: 10V  ValueDisplayed: 22uF  [0603L]  (hidden comment: C1608X5R1A226M080AC)
C61  VDC_V: 16V  ValueDisplayed: 0.1uF  [0402L]  (hidden comment: 885012205037)
C62  VDC_V: 10V  ValueDisplayed: 10uF  [0603L]  (hidden comment: C1608X5R1A106M080AC)
C63  ValueDisplayed: 1uF  [0402L]  (hidden comment: GRM152R60J105ME15D)
C64  VDC_V: 16V  ValueDisplayed: 0.01uF  [0402L]  (hidden comment: 885012205031)
C65  VDC_V: 16V  ValueDisplayed: 0.1uF  [0402L]  (hidden comment: 885012205037)
C66  VDC_V: 16V  ValueDisplayed: 0.1uF  [0402L]  (hidden comment: 885012205037)
C67  VDC_V: 16V  ValueDisplayed: 0.1uF  [0402L]  (hidden comment: 885012205037)
C68  VDC_V: 16V  ValueDisplayed: 0.1uF  [0402L]  (hidden comment: 885012205037)
C69  VDC_V: 16V  ValueDisplayed: 0.1uF  [0402L]  (hidden comment: 885012205037)
C70  VDC_V: 16V  ValueDisplayed: 0.1uF  [0402L]  (hidden comment: 885012205037)
C71  VDC_V: 16V  ValueDisplayed: 0.1uF  [0402L]  (hidden comment: 885012205037)
C72  VDC_V: 16V  ValueDisplayed: 0.1uF  [0402L]  (hidden comment: 885012205037)
C73  VDC_V: 16V  ValueDisplayed: 0.1uF  [0402L]  (hidden comment: 885012205037)
C74  VDC_V: 16V  ValueDisplayed: 0.1uF  [0402L]  (hidden comment: 885012205037)
C75  VDC_V: 16V  ValueDisplayed: 0.1uF  [0402L]  (hidden comment: 885012205037)
C76  VDC_V: 16V  ValueDisplayed: 0.1uF  [0402L]  (hidden comment: 885012205037)
C77  VDC_V: 16V  ValueDisplayed: 0.1uF  [0402L]  (hidden comment: 885012205037)
C78  VDC_V: 16V  ValueDisplayed: 0.1uF  [0402L]  (hidden comment: 885012205037)
C79  VDC_V: 16V  ValueDisplayed: 0.1uF  [0402L]  (hidden comment: 885012205037)
C80  VDC_V: 16V  ValueDisplayed: 0.1uF  [0402L]  (hidden comment: 885012205037)
C81  VDC_V: 16V  ValueDisplayed: 0.1uF  [0402L]  (hidden comment: 885012205037)
C82  VDC_V: 16V  ValueDisplayed: 0.1uF  [0402L]  (hidden comment: 885012205037)
C83  VDC_V: 16V  ValueDisplayed: 0.1uF  [0402L]  (hidden comment: 885012205037)
C84  ValueDisplayed: 470pF  [0402L]  (hidden comment: GRM1555C1H471JA01D)
C85  VDC_V: 16V  ValueDisplayed: 0.1uF  [0402L]  (hidden comment: 885012205037)
C86  VDC_V: 16V  ValueDisplayed: 0.1uF  [0402L]  (hidden comment: 885012205037)
C87  ValueDisplayed: 2.2uF  VDC_V: 10V  [0603L]  (hidden comment: Capacitor)
C88  VDC_V: 16V  ValueDisplayed: 0.1uF  [0402L]  (hidden comment: 885012205037)
C89  VDC_V: 16V  ValueDisplayed: 0.1uF  [0402L]  (hidden comment: 885012205037)
C90  VDC_V: 16V  ValueDisplayed: 0.1uF  [0402L]  (hidden comment: 885012205037)
C91  VDC_V: 16V  ValueDisplayed: 0.1uF  [0402L]  (hidden comment: 885012205037)
C92  VDC_V: 16V  ValueDisplayed: 0.1uF  [0402L]  (hidden comment: 885012205037)
D2  USB RDY  value Blue  [LTST-C170TBKT_Blue]
J22  SCL  [PBC03SAAN]
J23  SDA  [PBC03SAAN]
J24  JTAG  [SULLINS_LPPB061NGCN-RC]
J25  USB  [Molex_0475890001]
L6  ValueDisplayed: 2.2uH  [1008]  (hidden comment: LQM2HPN2R2MG0L)
L7  MPZ2012S601AT000  [MPZ2012]  (value not drawn)
L8  MPZ2012S601AT000  [MPZ2012]  (value not drawn)
R34  ValueDisplayed: 66.5k  [0603L]  (hidden comment: RC0603FR-0766K5L)
R35  ValueDisplayed: 100k  [0603L]  (hidden comment: RC0603FR-07100KL)
R36  ValueDisplayed: 1.0k  [0402L]  (hidden comment: Resistor)
R37  ValueDisplayed: 2.2k  [0402L]  (hidden comment: Resistor)
R38  ValueDisplayed: 2.2k  [0402L]  (hidden comment: Resistor)
R39  ValueDisplayed: 10.0k  [0402L]  (hidden comment: Resistor)
R40  ValueDisplayed: 4.7  [0603L]  (hidden comment: Resistor)
R41  ValueDisplayed: 10k  [0402L]  (hidden comment: Resistor)
R42  ValueDisplayed: 33.2  [0201L]  (hidden comment: Resistor)
R43  ValueDisplayed: 33.2  [0201L]  (hidden comment: Resistor)
R44  ValueDisplayed: 33.2  [0201L]  (hidden comment: Resistor)
R45  ValueDisplayed: 680  [0603L]  (hidden comment: RC0603FR-07680RL)
R46  ValueDisplayed: 10.0k  [0402L]  (hidden comment: Resistor)
R47  ValueDisplayed: 33.2  [0201L]  (hidden comment: Resistor)
R48  ValueDisplayed: 0  [0201L]  (hidden comment: ERJ-1GN0R00C)
R49  ValueDisplayed: 43.2  [0402L]  (hidden comment: ERJ2RKF43R2X)
R50  ValueDisplayed: 10.0k  [0201]  (hidden comment: Resistor)
R51  ValueDisplayed: 10.0k  [0201]  (hidden comment: Resistor)
R52  ValueDisplayed: 33.2  [0201L]  (hidden comment: Resistor)
R53  ValueDisplayed: 33.2  [0201]  (hidden comment: Resistor)
R54  ValueDisplayed: 25.5k  [0201]  (hidden comment: Resistor)
R55  ValueDisplayed: 10.0k  [0201]  (hidden comment: Resistor)
R56  ValueDisplayed: 33.2  [0201]  (hidden comment: Resistor)
R57  ValueDisplayed: 10.0k  [0201]  (hidden comment: Resistor)
R58  ValueDisplayed: 51.0k  [0201]  (hidden comment: Resistor)
R59  ValueDisplayed: 47.0k  [0402L]  (hidden comment: Resistor)
TP13  SCL_XMOS  [Keystone5003]
TP14  SDA_XMOS  [Keystone5003]
TP19  SCL_AMP  [Keystone5003]
TP20  SDA_AMP  [Keystone5003]
U4  TLV62568DBVR  [DBV0005A_N]
U5  PartNumber: TPS73618DBVR  [DBV0005A_N]  (hidden comment: TPS736xxDBV)
U6  XEF216-512-TQ128-C20A  [TQFP-128]  (parts A,B,C,D,E of 5)
U7  TCA9406DCUR  [DCU0008A_N]
U8  CDCE913PWR  [PW0014A_L]
U9  SN74AVC2T244  [DQM0008A]
U10  PartNumber: SN74LVC2G07DSFR  [DSF0006A]  (hidden comment: SN74LVC2G07)
U11  TPS3897ADRYR  [DRY0006A]
Y1  Frequency_Fixed: 24MHz  [FP-ASA-24.000MHZ-L-T_SMD_2MM0_1MM6-MFG]  (hidden comment: ASA-24.000MHZ-L-T)

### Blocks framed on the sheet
3.3V to 1.8V LDO: C62-C64 U5
3.3V to 1V BUCK LDO for XMOS: C58-C61 L6 R34 R35 U4
XMOS AND I/Os: C79-C83 D2 J22 J23 R36-R49 TP13 TP14 TP19 TP20 U6 U7
JTAG: C84-C86 J24 R50 R51 R54 R55 R58 U10 U11
CLOCK GENERATION: C88-C92 R52 R53 R56 R57 U8 U9 Y1
USB I/O: C87 J25 L7 L8 R59

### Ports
AMP_SCL (bidir), AMP_SDA (bidir), BCLK-XMOS (out), DOUT-XMOS (out), LRCLK-XMOS (out), SCL (bidir), SCL_XMOS (bidir), SDA (bidir), SDA_XMOS (bidir), SDIN-XMOS (in), X-TCK (bidir), X-TDI (bidir), X-TDO (bidir), X-TMS (bidir), X-TRSTN (bidir)

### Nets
1.0V: C59.1 C60.1 C61.1 C65.2 C66.2 C67.2 C68.2 C69.2 C70.2 C71.2 C72.2 C73.2 C74.2 C75.2 C76.2 C77.2 C78.2 L6.2 R34.2 R40.1 R54.1 U6.11(VDD) U6.16(VDD) U6.17(VDD) U6.24(VDD) U6.36(VDD) U6.41(VDD) U6.49(USB_VDD) U6.56(VDD) U6.60(VDD) U6.73(VDD) U6.80(VDD) U6.81(VDD) U6.87(VDD) U6.101(VDD) U6.102(VDD) U6.120(VDD) U6.126(VDD)
1.8V: C63.2 C91.2 C92.2 U5.5(OUT) U8.3(VDD) U9.8(VCCB)
3.3V: C44.2 C45.2 C46.2 C47.2 C48.2 C49.2 C50.2 C51.2 C52.2 C53.2 C54.2 C55.2 C56.2 C57.2 C58.1 C62.1 C81.2 C85.2 C86.2 C88.2 C89.2 C90.2 R36.1 R37.1 R38.1 R41.2 R45.2 R50.1 R51.1 R55.1 R57.1 U4.1(EN) U4.4(VIN) U5.1(IN) U5.3(EN) U6.6(VDDIOL) U6.14(VDDIOL) U6.19(VDDIOL) U6.29(VDDIOL) U6.42(VDDIOL) U6.44(USB_VDD33) U6.52(VDDIOR) U6.67(VDDIOR) U6.78(VDDIOR) U6.83(VDDIOR) U6.92(VDDIOR) U6.105(OTP_VCC) U6.110(VDDIOT) U6.111(VDDIOT) U7.7(VCCB) U8.6(VDDOUT) U8.7(VDDOUT) U9.1(VCCA) U10.5(VCC) U11.1(ENABLE) U11.6(VCC) Y1.4(VDD)
5V-SPDIF: L7.2
GND: C44.1 C45.1 C46.1 C47.1 C48.1 C49.1 C50.1 C51.1 C52.1 C53.1 C54.1 C55.1 C56.1 C57.1 C58.2 C59.2 C60.2 C61.2 C62.2 C63.1 C64.1 C65.1 C66.1 C67.1 C68.1 C69.1 C70.1 C71.1 C72.1 C73.1 C74.1 C75.1 C76.1 C77.1 C78.1 C79.1 C80.1 C81.1 C82.2 C83.2 C84.1 C85.1 C86.1 C87.1 C88.1 C89.1 C90.1 C91.1 C92.1 J22.3 J23.3 J24.6 L8.2 R35.1 R49.1 R58.2 R59.1 U4.2(GND) U5.2(GND) U6.104(PLL_AGND) U6.129(PADDLE_GND) U7.2(GND) U8.2(S0) U8.5(GND) U8.10(GND) U9.3(A2) U9.4(~{OE}) U9.5(GND) U10.2(GND) U11.2(GND) Y1.2(GND)
IOVDD: C79.2 C80.2 R39.2 U7.3(VCCA)
~{TRST}: R48.1 U6.123(~{TRST})
AMP_SCL: J22.1 TP19.1 ; port AMP_SCL
AMP_SDA: J23.1 TP20.1 ; port AMP_SDA
BCLK-XMOS: R43.2 R52.2 ; port BCLK-XMOS
DOUT-XMOS: R47.2 ; port DOUT-XMOS
GND-USB: J25.5(GND) J25.6 J25.7 J25.8 J25.9 J25.10 J25.11 L8.1
LRCLK-XMOS: R42.2 ; port LRCLK-XMOS
MCLK-XMOS: R53.1 U6.13(X1D35) U6.63(X0D13)
SCL: R37.2 U6.37(X0D02) U7.8(SCL_B) ; port SCL
SCL_XMOS: J22.2 TP13.1 U7.5(SCL_A) U8.12(SCL/S2) ; port SCL_XMOS
SDA: R38.2 U6.38(X0D03) U7.1(SDA_B) ; port SDA
SDA_XMOS: J23.2 TP14.1 U7.4(SDA_A) U8.13(SDA/S1) ; port SDA_XMOS
SDIN-XMOS: R44.2 ; port SDIN-XMOS
SW: L6.1 U4.3(SW)
USB_D_M: J25.2(D-) U6.47(USB_DM)
USB_D_P: J25.3(D+) U6.46(USB_DP)
USB_ID: J25.4(ID) U6.43(USB_ID)
VBUS-XMOS: C83.1 R46.1 U6.45(USB_VBUS)
VBUS_IN: C87.2 J25.1(VBUS) L7.1 R46.2 R59.2
X-24M: R56.2 U6.125(CLK) U9.2(A1)
X-HS-EN: R41.1 U6.55(X1D21)
X-RSTN: R48.2 R51.2 U6.124(~{RST}) U10.4(2Y) U10.6(1Y)
X-TCK: J24.1 U6.128(TCK) ; port X-TCK
X-TDI: J24.3 U6.2(TDI) ; port X-TDI
X-TDO: J24.4 U6.1(TDO) ; port X-TDO
X-TMS: J24.2 U6.127(TMS) ; port X-TMS
X-TRSTN: J24.5 R50.2 U10.1(1A) ; port X-TRSTN
XIN/CLK: U8.1(XIN/CLK) U9.7(B1)
NetC64_2: C64.2 U5.4(NR/FB)
NetC82_1: C82.1 R40.2 U6.103(PLL_AVDD)
NetC84_2: C84.2 U11.5(CT)
NetD2_1: D2.1(A) R45.1
NetD2_2: D2.2(K) U6.116(X1D30)
NetR34_1: R34.1 R35.2 U4.5(FB)
NetR36_2: R36.2 U6.27(X0D01)
NetR39_1: R39.1 U7.6(OE)
NetR42_1: R42.1 U6.64(X0D22)
NetR43_1: R43.1 U6.66(X0D23)
NetR44_1: R44.1 U6.88(X0D24)
NetR47_1: R47.1 U6.3(X0D36)
NetR49_2: R49.2 U6.48(USB_RTUNE)
NetR52_1: R52.1 U8.11(Y1)
NetR53_2: R53.2 U8.9(Y2)
NetR54_2: R54.2 R58.1 U11.3(SENSE)
NetR55_2: R55.2 U10.3(2A) U11.4(SENSE_OUT)
NetR56_1: R56.1 Y1.3(Output)
NetR57_2: R57.2 Y1.1(~{Tri-State})

Not connected (* = marked no-connect by the designer): U6 4(X0D37) 5(X0D38) 7(X0D39) 8(X0D40) 9(X0D41) 10(X0D42) 12(X0D43) 15(X1D36) 18(X1D37) 20(X1D38) 21(X1D39) 22(X1D16) 23(X1D17) 25(X1D18) 26(X1D19) 28(X0D10) 30(X0D00) 31(X0D04) 32(X0D11) 33(X0D05) 34(X0D06) 35(X0D07) 39(X0D08) 40(X0D09) 50(NC)* 51(X1D14) 53(X1D15) 54(X1D20) 57(X0D14) 58(X0D15) 59(X0D20) 61(X0D21) 62(X0D12) 65(NC)* 68(X0D16) 69(X0D17) 70(X0D18) 71(X0D19) 72(X1D02) 74(X1D03) 75(X1D04) 76(X1D05) 77(X1D06) 79(X1D07) 82(X1D08) 84(X1D09) 85(X1D00) 86(X1D01) 89(X0D25) 90(X0D34) 91(X0D35) 93(X0D26) 94(X0D27) 95(X0D32) 96(X0D28) 97(X0D33) 98(X0D29) 99(X0D30) 100(X0D31) 106(X1D40) 107(X1D41) 108(X1D42) 109(X1D43) 112(X1D26) 113(X1D27) 114(X1D28) 115(X1D29) 117(X1D31) 118(X1D32) 119(X1D33) 121(X1D10) 122(X1D11); U8 4(VCTR)* 8(Y3) 14(XOUT); U9 6(B2)

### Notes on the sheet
- OUTPUT = 1.8V@400mA
- OUTPUT = 1.0V@1A
- I2C
- I2S TO MUXES

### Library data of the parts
C44-C57 C61 C65-C83 C85 C86 C88-C92 = CMP-0006228-2: CAP, CERM, 0.1 uF, 16 V, +/- 10%, X7R, 0402; Manufacturer: Wurth Elektronik; TaMin_C: -55°C; Polarized: N; SizeAreaWB_mm2: 3; Value1: Unknown; U/M: EA; Value: 0.1uF; TaMax_C: 125°C; SizeZ_mm: 0.6; SizeX_mm: 1; SizeY_mm: 0.5; Cap_Case: 0402; Cap_F: 100nF; AEC Category: Q200
C58-C60 = CMP-0007005-5: CAP, CERM, 22 uF, 10 V, +/- 20%, X5R, 0603; Manufacturer: TDK; TaMin_C: -55°C; ESR_ohm: 3.71m; Polarized: N; SizeAreaWB_mm2: 4.68; Value1: 0.00371 ohm; U/M: EA; Value: 22uF; TaMax_C: 85°C; SizeZ_mm: 1; SizeX_mm: 1.6; SizeY_mm: 0.8; Cap_Case: 0603; SizeArea_mm2: 1.28; CompType: Capacitor; Cap_F: 22µF; IRMS_A: 2.69936A; AEC Category: Q200
C62 = CMP-0007003-5: CAP, CERM, 10 uF, 10 V, +/- 20%, X5R, 0603; Manufacturer: TDK; TaMin_C: -55°C; ESR_ohm: 7.8m; Polarized: N; SizeAreaWB_mm2: 4.68; Value1: 0.0078 ohm; U/M: EA; Value: 10uF; TaMax_C: 85°C; SizeZ_mm: 1; SizeX_mm: 1.6; SizeY_mm: 0.8; Cap_Case: 0603; SizeArea_mm2: 1.28; CompType: Capacitor; Cap_F: 10µF; IRMS_A: 1.85A; AEC Category: Q200
C63 = CMP-0006372-2: CAP, CERM, 1 uF, 6.3 V, +/- 20%, X5R, 0402; Manufacturer: MuRata; TaMin_C: -55°C; Polarized: N; SizeAreaWB_mm2: 3; Value1: Unknown; U/M: EA; Value: 1uF; TaMax_C: 85°C; SizeZ_mm: 0.6; SizeX_mm: 1; SizeY_mm: 0.5; Cap_Case: 0402; Value2: 6.3V; CompType: Capacitor; Cap_F: 1µF; AEC Category: Q200
C64 = CMP-0006227-2: CAP, CERM, 0.01 uF, 16 V, +/- 10%, X7R, 0402; Manufacturer: Wurth Elektronik; TaMin_C: -55°C; Polarized: N; SizeAreaWB_mm2: 3; Value1: Unknown; U/M: EA; Value: 0.01uF; TaMax_C: 125°C; SizeZ_mm: 0.6; SizeX_mm: 1; SizeY_mm: 0.5; Cap_Case: 0402; Cap_F: 10nF; AEC Category: Q200
C84 = CMP-0006470-2: CAP, CERM, 470 pF, 50 V, +/- 5%, C0G/NP0, 0402; Manufacturer: MuRata; TaMin_C: -55°C; Polarized: N; SizeAreaWB_mm2: 3; Value1: Unknown; U/M: EA; Value: 470pF; TaMax_C: 125°C; SizeZ_mm: 0.6; SizeX_mm: 1; SizeY_mm: 0.5; Cap_Case: 0402; Value2: 50V; AEC Category: Q200
C87 = CMP-0007370-4: CAP, CERM, 2.2 uF, 10 V, +/- 10%, X7R, 0603; PartNumber: GRM188R71A225KE15D; Manufacturer: MuRata; Polarized: N; Value: 2.2uF; U/M: EA; Cap_F: 2.2µF; ESR_ohm: 9m; Value1: 0.009 ohm; TaMin_C: -55°C; TaMax_C: 125°C; Cap_Case: 0603; SizeArea_mm2: 1.28; SizeAreaWB_mm2: 4.68; SizeX_mm: 1.6; SizeY_mm: 0.8; SizeZ_mm: 1; AEC Category: Q200
D2 = CMP-0002889-2: LED, Blue, SMD; PartNumber: LTST-C170TBKT; Manufacturer: Lite-On; Type: AlInGaP; Value1: W; Io_A: 20mA; Vf_V: 3.3V
J22 J23 = CMP-0002334-1: Header, 100mil, 3x1, Gold, TH; Manufacturer: Sullins Connector Solutions; Green_Lifecycle: Not Set; Green_REACh: Incomplete; CNHeader: TRUE; CT: FALSE
J24 = CMP-0054640-1: Receptacle, 50mil, 6x1, Gold, R/A, TH; PartNumber: LPPB061NGCN-RC; Manufacturer: Sullins Connector Solutions; CompType: Socket Strip; Pitch_mm: 1.27; Gender: Female; Row_Count: 1; CNHeader: FALSE; CT: TRUE; Green_Lifecycle: Active; Green_REACh: Passed
J25 = CMP-0055301-1: Connector, Receptacle, Micro-USB Type AB, R/A, Bottom Mount SMT; Manufacturer: Molex; PartNumber: 475890001; CT: TRUE; Green_REACh: Passed; CNHeader: FALSE; Green_Lifecycle: Active; Gender: Female
L6 = CMP-0058752-1: Inductor, Multilayer, Ferrite, 2.2 uH, 1.3 A, 0.08 ohm, SMD; Manufacturer: MuRata; Irms: 1.3A @ 40C rise; Green_Lifecycle: Active; SizeAreaWB_mm2: 10.5; DCR_ohm: 0.08; Green_REACh: Passed; Value: 2.2uH; Imax_A: 1.3A; SizeZ_mm: 1.2; SizeX_mm: 2.5; SizeY_mm: 2; SizeArea_mm2: 5; Ind_H: 2.2µH; AEC Category: Q200
L7 L8 = CMP-0003429-3: Ferrite Bead, 600 ohm @ 100 MHz, 2 A, 0805; Manufacturer: TDK; ZTyp@100MHz_Ohm: 600; SizeAreaWB_mm2: 6.75; DCR_ohm: 1d; Value1: 0.1 ohm; Value: 600 ohm; Imax_A: 2A; SizeZ_mm: 1.45; SizeX_mm: 2; SizeY_mm: 1.25; SizeArea_mm2: 2.5
R34 = CMP-0023232-5: RES, 66.5 k, 1%, 0.1 W, 0603; Manufacturer: Yageo; Power_W: 100mW; TempCo: 100 ppm/C; Value_Code: 66k5; Value: 66.5k; EIA_Code: E96; SizeZ_mm: 1; Value2: 0.1W; SizeArea_mm2: 1.28; AEC Qualified: N; VDC_V: 75V; AEC Category: Q200; SizeAreaWB_mm2: 4.68; SizeX_mm: 1.6; SizeY_mm: 0.8
R35 = CMP-0022735-5: RES, 100 k, 1%, 0.1 W, 0603; Manufacturer: Yageo; Power_W: 100mW; TempCo: 100 ppm/C; Value: 100k; EIA_Code: E96; SizeX_mm: 1.6; SizeY_mm: 0.8; SizeZ_mm: 1; Value2: 0.1W; SizeArea_mm2: 1.28; AEC Qualified: N; VDC_V: 75V; AEC Category: Q200; SizeAreaWB_mm2: 4.68
R36 = CMP-0026852-3: RES, 1.0 k, 5%, 0.063 W, AEC-Q200 Grade 0, 0402; PartNumber: CRCW04021K00JNED; Manufacturer: Vishay-Dale; Alternate Manufacturer: Vishay Dale; Alternate PartNumber: CRCW04021K00JNTD; Value: 1.0k; Res_ohm: 1k; Value_Code: 1k00; Power_W: 63mW; Value2: 0.063W; VDC_V: 50V; TempCo: 200 ppm/C; EIA_Code: E24; AEC Category: Q200; AEC Qualified: Y; AEC Grade: 0; SizeArea_mm2: 0.5; SizeX_mm: 1; SizeZ_mm: 0.6
R37 R38 = CMP-0026890-5: RES, 2.2 k, 5%, 0.063 W, AEC-Q200 Grade 0, 0402; PartNumber: CRCW04022K20JNED; Manufacturer: Vishay-Dale; Value: 2.2k; Value_Code: 2k20; Power_W: 63mW; Value2: 0.063W; VDC_V: 50V; TempCo: 200 ppm/C; EIA_Code: E24; AEC Category: Q200; AEC Qualified: Y; AEC Grade: 0; SizeArea_mm2: 0.5; SizeX_mm: 1; SizeZ_mm: 0.6
R39 R46 = CMP-0026658-1: RES, 10.0 k, 1%, 0.1 W, 0402; PartNumber: ERJ-2RKF1002X; Manufacturer: Panasonic; Alternate PartNumber: ERJ-U02F1002X; Value: 10.0k; Res_ohm: 10k; Value_Code: 10k0; Power_W: 100mW; Value2: 0.1W; VDC_V: 50V; TempCo: 100 ppm/C; EIA_Code: E96; U/M: EA; AEC Category: Q200; SizeArea_mm2: 0.5; SizeX_mm: 1; SizeZ_mm: 0.6
R40 = CMP-0025821-4: RES, 4.7, 5%, 0.1 W, AEC-Q200 Grade 0, 0603; PartNumber: CRCW06034R70JNEA; Manufacturer: Vishay-Dale; Value: 4.7; Value_Code: 4R70; Power_W: 100mW; Value2: 0.1W; VDC_V: 75V; TempCo: 200 ppm/C; EIA_Code: E24; AEC Category: Q200; AEC Qualified: Y; AEC Grade: 0; SizeArea_mm2: 1.28; SizeX_mm: 1.6; SizeY_mm: 0.8; SizeZ_mm: 1
R41 = CMP-0026825-5: RES, 10 k, 5%, 0.063 W, AEC-Q200 Grade 0, 0402; PartNumber: CRCW040210K0JNED; Manufacturer: Vishay-Dale; Alternate Manufacturer: Panasonic; Alternate PartNumber: ERJ-U02F1002X; Value: 10k; Value_Code: 10k0; Power_W: 63mW; Value2: 0.063W; VDC_V: 50V; TempCo: 200 ppm/C; EIA_Code: E24; AEC Category: Q200; AEC Qualified: Y; AEC Grade: 0; SizeArea_mm2: 0.5; SizeX_mm: 1; SizeZ_mm: 0.6
R42-R44 R47 R52 = CMP-0027614-1: RES, 33.2, 1%, 0.05 W, 0201; PartNumber: RC0201FR-0733R2L; Manufacturer: Yageo America; Value: 33.2; Value_Code: 33R2; Power_W: 50mW; Value2: 0.05W; VDC_V: 25V; TempCo: 200 ppm/C; SizeArea_mm2: 0.18; SizeX_mm: 0.6; SizeY_mm: 0.3; SizeZ_mm: 0.26; EIA_Code: E96; U/M: EA; AEC Category: Q200; AEC Qualified: N
R45 = CMP-0023235-5: RES, 680, 1%, 0.1 W, 0603; Manufacturer: Yageo; Power_W: 100mW; TempCo: 100 ppm/C; Value_Code: 680R; Value: 680; SizeX_mm: 1.6; SizeY_mm: 0.8; SizeZ_mm: 1; Value2: 0.1W; SizeArea_mm2: 1.28; AEC Qualified: N; VDC_V: 75V; AEC Category: Q200; SizeAreaWB_mm2: 4.68
R48 = CMP-0065361-1: RES, 0, 5%, .05 W, AEC-Q200 Grade 0, 0201; Manufacturer: Panasonic; Power_W: 50mW; TempCo: ppm/C; Value_Code: 0000; Value: 0; EIA_Code: E24; SizeX_mm: 0.6; SizeY_mm: 0.3; SizeZ_mm: 0.26; Value2: .05W; SizeArea_mm2: 0.18; AEC Qualified: Y; AEC Category: Q200; Green_Lifecycle: Not Set; Green_REACh: Incomplete; U/M: EA
R49 = CMP-0082538-1: RES, 43.2, 1%, 0.1 W, AEC-Q200 Grade 0, 0402; Manufacturer: Panasonic; Power_W: 100mW; TempCo: 100 ppm/C; SizeAreaWB_mm2: 3; Value_Code: 43R2; Value: 43.2; EIA_Code: E96; SizeX_mm: 1; SizeY_mm: 0.5; SizeZ_mm: 0.6; Value2: 0.1W; CompType: Resistor; AEC Qualified: Y; VDC_V: 50V; AEC Grade: 0; AEC Category: Q200
R50 R51 R55 R57 = CMP-0027262-3: RES, 10.0 k, 1%, 0.05 W, 0201; PartNumber: CRCW020110K0FKED; Manufacturer: Vishay-Dale; Value: 10.0k; Res_ohm: 10k; Value_Code: 10k0; Power_W: 50mW; Value2: 0.05W; VDC_V: 30V; TempCo: 100 ppm/C; SizeArea_mm2: 0.18; SizeX_mm: 0.6; SizeY_mm: 0.3; SizeZ_mm: 0.26; EIA_Code: E96; AEC Category: Q200; AEC Qualified: N
R53 R56 = CMP-0027614-1: RES, 33.2, 1%, 0.05 W, 0201; PartNumber: RC0201FR-0733R2L; Manufacturer: Yageo America; Value: 33.2; Value_Code: 33R2; Power_W: 50mW; Value2: 0.05W; VDC_V: 25V; TempCo: 200 ppm/C; EIA_Code: E96; U/M: EA; SizeArea_mm2: 0.18; SizeX_mm: 0.6; SizeY_mm: 0.3; SizeZ_mm: 0.26; AEC Category: Q200; AEC Qualified: N
R54 = CMP-0027523-1: RES, 25.5 k, 1%, 0.05 W, 0201; PartNumber: RC0201FR-0725K5L; Manufacturer: Yageo America; Value: 25.5k; Value_Code: 25k5; Power_W: 50mW; Value2: 0.05W; VDC_V: 25V; TempCo: 200 ppm/C; SizeArea_mm2: 0.18; SizeX_mm: 0.6; SizeY_mm: 0.3; SizeZ_mm: 0.26; EIA_Code: E96; U/M: EA; AEC Category: Q200; AEC Qualified: N
R58 = CMP-0027757-1: RES, 51.0 k, 1%, 0.05 W, 0201; PartNumber: RC0201FR-0751KL; Manufacturer: Yageo America; Value: 51.0k; Res_ohm: 51k; Value_Code: 51k0; Power_W: 50mW; Value2: 0.05W; VDC_V: 25V; TempCo: 200 ppm/C; SizeArea_mm2: 0.18; SizeX_mm: 0.6; SizeY_mm: 0.3; SizeZ_mm: 0.26; U/M: EA; AEC Category: Q200; AEC Qualified: N
R59 = CMP-0026737-1: RES, 47.0 k, 1%, 0.0625 W, 0402; PartNumber: RC0402FR-0747KL; Manufacturer: Yageo America; Value: 47.0k; Res_ohm: 47k; Value_Code: 47k0; Power_W: 62.5mW; VDC_V: 50V; TempCo: 100 ppm/C; U/M: EA; AEC Category: Q200; AEC Qualified: N; SizeArea_mm2: 0.5; SizeX_mm: 1; SizeZ_mm: 0.6
TP13 TP14 TP19 TP20 = CMP-0055140-2: as TP5 on sheet AMPS262A_PowerSupplies
U4 = CMP-0013046-2: 1-A High Efficiency Step-Down Converter in SOT23-5 Package, DBV005A, DBV0005A (SOT-5); Manufacturer: Texas Instruments; Alternate PartNumber: TLV62568DBVT; SizeX_mm: 2.8; SizeY_mm: 2.9; CompType: IC; SizeZ_mm: 1.45; SizeArea_mm2: 8.12; SizeAreaWB_mm2: 14.82; U/M: EA
U5 = CMP-0036854-2: Single Output LDO, 400mA, Adj.(1.2 to 5.5V), Cap free, Low Noise, Reverse Current Protection, DBV0005A (SOT-23-5); Manufacturer: Texas Instruments; Accuracy(%): 1; Eco-Plan: Green (RoHS & no Sb/Br); Fixed Output Options(V): 1.8; Iout(Max)(A): 0.4; Iq(Typ)(mA): 0.3; Rating: Catalog; SubFamily: Single Channel LDO; Vdo(Typ)(mV): 75; Vin(Max)(V): 5.5; Vin(Min)(V): 1.7; AEC Category: Q200; AEC Qualified: N; CompType: IC; Green_Lifecycle: Active; Green_REACh: Passed; SizeArea_mm2: 8.12; SizeAreaWB_mm2: 14.82; SizeX_mm: 2.8; SizeY_mm: 2.9; SizeZ_mm: 1.45
U6 = CMP-0092035-2: XCore XEF Microcontroller IC 32-Bit 16-Core 2000MIPs 2MB (2M x 8) FLASH 128-TQFP (14x14); Manufacturer: XMOS; SizeZ_mm: 1.2mm; Frequency_Fixed: 24MHz; TJmax_C: +125°C; TaMax_C: +70°C; Min Supply Voltage: 950mV; Memory Size: 2MBytes; Number Of Usb Channels: 1; AEC Qualified: No; Number Of Cores: 16; Data Bus Width: 32bits; Number Of Timers/Counters: 20; Standoff Height: 0.05mm; Number Of I/Os: 81; TaMin_C: 0°C; Ram Size: 512KBytes; Max Supply Voltage: 3.465V; Nominal Supply Current: 570mA; Interface: USB,Other
U7 = CMP-0043323-2: 2-Bit Bidirectional 1-MHz I2C Bus and SMBus Voltage-Level Shifter, DCU0008A (VSSOP-8); Manufacturer: Texas Instruments; VCC(Min)(V): -0.5; 5V Tolerant I/O: Yes; Max Frequency(kHz): 1000; Function: I2C Voltage Level Translator; Vcc range(V): 1.65 to 3.6; No. of Outputs: 2; Eco-Plan: Green (RoHS & no Sb/Br); On-Chip Power-on-Reset: No; VCC(Max)(V): 4.6; Rating: Catalog; AEC Category: Q200; AEC Qualified: N; CompType: IC; SizeAreaWB_mm2: 12.6; SizeArea_mm2: 6.4; SizeX_mm: 3.2; SizeY_mm: 2.0; SizeZ_mm: 0.9
U8 = CMP-0065668-3: Programmable 1-PLL VCXO Clock Synthesizer with 2.5-V or 3.3-V LVCMOS Outputs, PW0014A (TSSOP-14); Alternate Manufacturer: Texas Instruments; AEC Category: Q200; SizeArea_mm2: 32.0; AEC Qualified: N; CompType: IC; Rating: Catalog; SizeY_mm: 5.0; SizeX_mm: 6.4; SizeZ_mm: 1.2; SizeAreaWB_mm2: 58.8
U9 = CMP-0050936-4: Dual-Bit Dual-Supply Bus Transceiver, DQM0008A (X2SON-8); Manufacturer: Texas Instruments; PartNumber: SN74AVC2T244DQMR; Output Type: CMOS; Bits(#): 2; Technology Family: AVC; Schmitt Trigger: No; VCC(Max)(V): 3.6; Sub-Family: Dual Supply Translator; Rating: Catalog; Output Drive (IOL/IOH)(Max)(mA): 24/-24; ICC @ Nom Voltage(Max)(mA): 0.0009; VCC(Min)(V): 0.9; F @ Nom Voltage(Max)(Mhz): 100; Logic: True; Voltage(Nom)(V): 0.9,1.2,1.5,1.8,2.5,3.3; tpd @ Nom Voltage(Max)(ns): 20,7,3.5; AEC Category: Q200; AEC Qualified: N; CompType: IC; Green_Lifecycle: Active; Green_REACh: Passed; SizeAreaWB_mm2: 6.16; SizeArea_mm2: 2.16; SizeX_mm: 1.2; SizeY_mm: 1.8; SizeZ_mm: 0.4
U10 = CMP-0051795-5: Enhanced Product Dual Buffer/Driver with Open-Drain Output, DCK0006A (SOT-SC70-6); Manufacturer: Texas Instruments; CompType: IC; 3-State Output: No; AEC Category: Q200; AEC Qualified: N; Bits(#): 2; F @ Nom Voltage(Max)(Mhz): 150; ICC @ Nom Voltage(Max)(mA): 0.01; Input Type: CMOS/TTL; Logic: True; Output Drive (IOL/IOH)(Max)(mA): 32/-32; Output Type: CMOS; Rating: Catalog; SizeArea_mm2: 1; SizeAreaWB_mm2: 4; SizeZ_mm: 0.4; Sub-Family: Inverting Buffer/Driver; Technology Family: LVC; tpd @ Nom Voltage(Max)(ns): 8.6,4.4,3.7,2.9; VCC(Max)(V): 5.5; VCC(Min)(V): 1.65; Voltage(Nom)(V): 1.8,2.5,3.3,5
U11 = CMP-0032427-3: Single-Channel Ultra-Small Adjustable Supervisory Circuit With Active-High Open-Drain Output, DRY0006A (USON-6); Manufacturer: Texas Instruments; Iq(Typ)(uA): 6; Time Delay(ms): 0.04, Programmable; VCC(Min)(V): 1.7; Reset Threshold Accuracy(%): 0.25; Enable Pin: TRUE; Output Driver Type / Reset Output: Active-High, Open-drain; # of Supplies Monitored: 1; Rating: Catalog; VCC(Max)(V): 6.5; AEC Category: Q200; AEC Qualified: N; CompType: IC; SizeAreaWB_mm2: 4.9; SizeArea_mm2: 1.45; SizeX_mm: 1.0; SizeZ_mm: 0.6
Y1 = CMP-0096068-1: Crystal Oscillator 24MHz ±50ppm HCMOS 3.3V SMD 2x1.6mm; Manufacturer: Abracon; AEC Qualified: No; SizeZ_mm: 0.8mm; Min Supply Voltage: 2.97V; Max Supply Voltage: 3.63V; Load Capacitance: 15pF; Max Supply Current: 5mA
